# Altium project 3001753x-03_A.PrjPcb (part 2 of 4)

## Sheet 07 - Console, CAN, RS485, RTC.SchDoc: Console, CAN, RS485, RTC
size A3; PageSetup: Record=PageOptions¦CenterHorizontal=True¦CenterVertical=True¦PrintScale=0.70¦XCorrection=1.00¦YCorrection=1.00¦PrintKind=0¦BorderSize=5000000¦LeftOffset=0¦BottomOffset=0¦Orientation=2¦PaperLength=4200¦PaperWidth=2970¦Scale=100¦PaperSource=7¦PrintQuality=600¦MediaType=1¦DitherType=10¦PaperKind=A4¦PrintScaleMode=1; Author: Juan Anzola; SheetNumber: 7; SheetTotal: 20
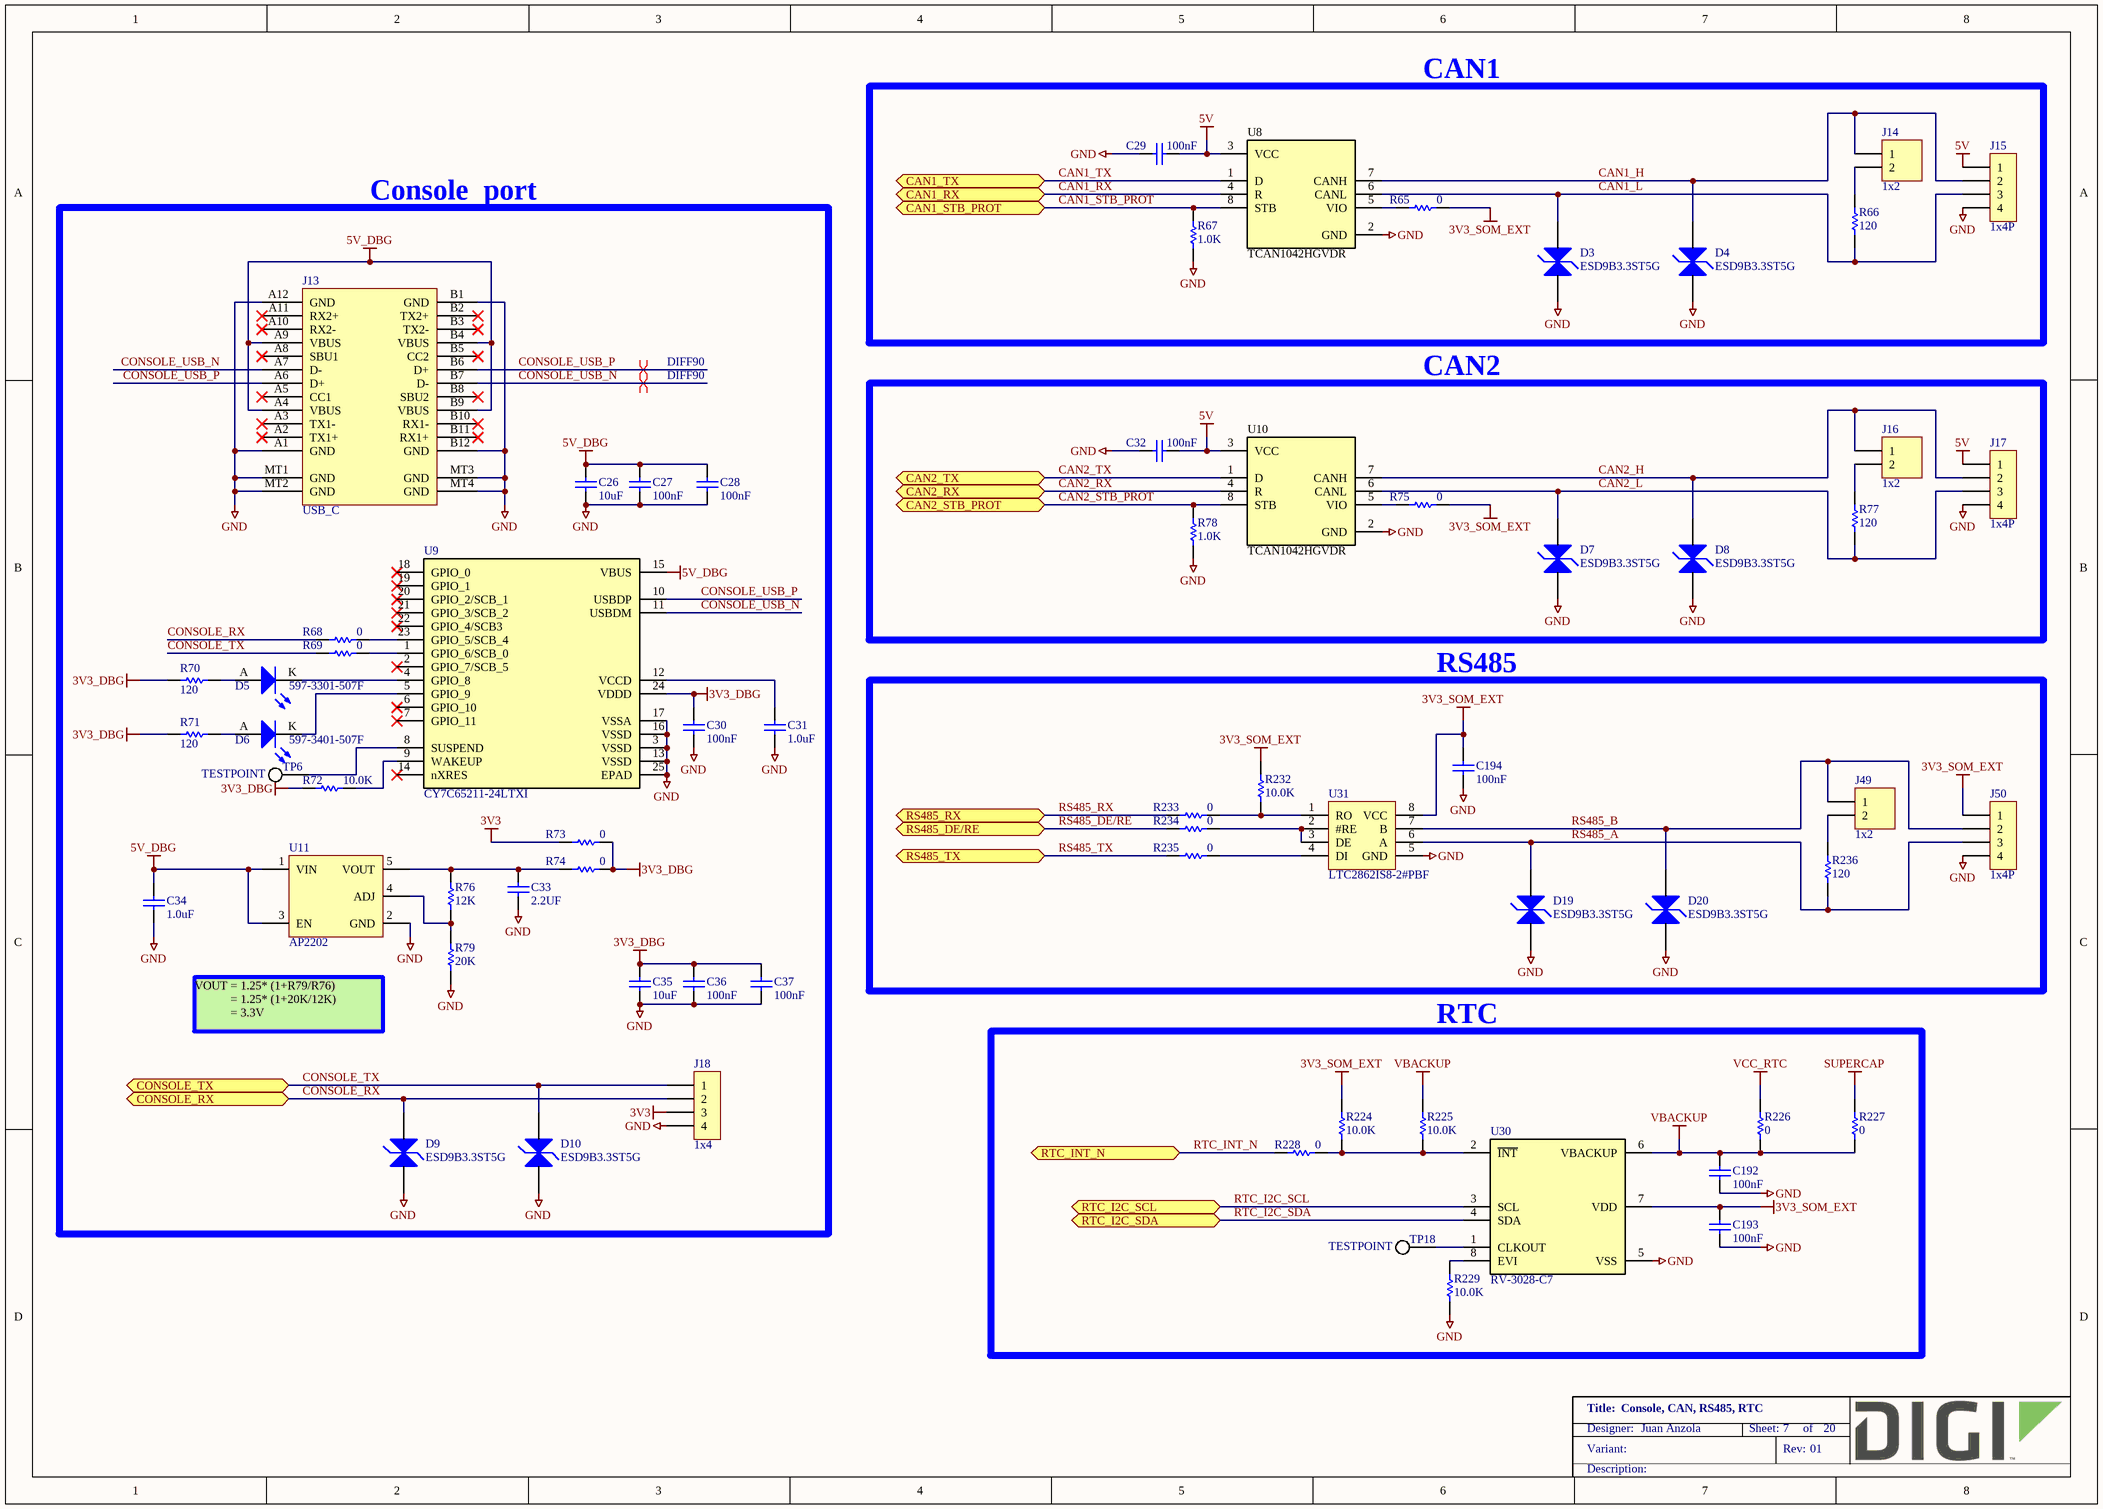
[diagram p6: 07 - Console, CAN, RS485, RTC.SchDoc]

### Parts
C26  10uF  [CAPC2013X135N]
C27  100nF  [CAPC1005X55N]
C28  100nF  [CAPC1005X55N]
C29  100nF  [CAPC1005X55N]
C30  100nF  [CAPC1005X55N]
C31  1.0uF  [CAPC1005X55N]
C32  100nF  [CAPC1005X55N]
C33  2.2UF  [CAPC1608X90N]
C34  1.0uF  [CAPC1005X55N]
C35  10uF  [CAPC2013X135N]
C36  100nF  [CAPC1005X55N]
C37  100nF  [CAPC1005X55N]
C192  100nF  [CAPC1005X55N]
C193  100nF  [CAPC1005X55N]
C194  100nF  [CAPC1005X55N]
D3  ESD9B3.3ST5G  [SODFL1006X43AN12]
D4  ESD9B3.3ST5G  [SODFL1006X43AN12]
D5  597-3301-507F  [LEDM3020X130N_GREEN]
D6  597-3401-507F  [LEDM3020X130N_YELLOW]
D7  ESD9B3.3ST5G  [SODFL1006X43AN12]
D8  ESD9B3.3ST5G  [SODFL1006X43AN12]
D9  ESD9B3.3ST5G  [SODFL1006X43AN12]
D10  ESD9B3.3ST5G  [SODFL1006X43AN12]
D19  ESD9B3.3ST5G  [SODFL1006X43AN12]
D20  ESD9B3.3ST5G  [SODFL1006X43AN12]
J13  USB_C  [MOLEX_201267-0005]
J14  1x2  [FCI_68002-102HLF]
J15  1x4P  [P4_STR_C2.54_H5.84]
J16  1x2  [FCI_68002-102HLF]
J17  1x4P  [P4_STR_C2.54_H5.84]
J18  1x4  [MOLEX_53047-0410]
J49  1x2  [FCI_68002-102HLF]
J50  1x4P  [P4_STR_C2.54_H5.84]
R65  0  [RESC1005X40N]
R66  120  [RESC1005X40N]
R67  1.0K  [RESC1005X40N]
R68  0  [RESC1005X40N]
R69  0  [RESC1005X40N]
R70  120  [RESC1005X40N]
R71  120  [RESC1005X40N]
R72  10.0K  [RESC1005X40N]
R73  0  [RESC1609X55N]
R74  0  [RESC1609X55N]
R75  0  [RESC1005X40N]
R76  12K  [RESC1609X55N]
R77  120  [RESC1005X40N]
R78  1.0K  [RESC1005X40N]
R79  20K  [RESC1609X55N]
R224  10.0K  [RESC1005X40N]
R225  10.0K  [RESC1005X40N]
R226  0  [RESC1005X40N]
R227  0  [RESC1005X40N]
R228  0  [RESC1005X40N]
R229  10.0K  [RESC1005X40N]
R232  10.0K  [RESC1005X40N]
R233  0  [RESC1005X40N]
R234  0  [RESC1005X40N]
R235  0  [RESC1005X40N]
R236  120  [RESC1005X40N]
TP6  TESTPOINT  [TP0762]  (no BOM)
TP18  TESTPOINT  [TP0762]  (no BOM)
U8  TCAN1042HGVDR  [SOIC127P600X175-8N]
U9  CY7C65211-24LTXI  [QFN50P400X400X100-25]
U10  TCAN1042HGVDR  [SOIC127P600X175-8N]
U11  AP2202  [SOT95P280X145-5N]
U30  RV-3028-C7  [DFN_8P_RV3028C7]
U31  LTC2862IS8-2#PBF  [SOIC127P600X175-8N]

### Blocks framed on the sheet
CAN1: C29 D3 D4 J14 J15 R65-R67 U8
Console  port: C26-C28 C30 C31 C33-C37 D5 D6 D9 D10 J13 J18 R68-R74 R76 R79 TP6 U9 U11
CAN2: C32 D7 D8 J16 J17 R75 R77 R78 U10
RS485: C194 D19 D20 J49 J50 R232-R236 U31
RTC: C192 C193 R224-R229 TP18 U30

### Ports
CAN1_RX (bidir), CAN1_STB_PROT (bidir), CAN1_TX (bidir), CAN2_RX (bidir), CAN2_STB_PROT (bidir), CAN2_TX (bidir), CONSOLE_RX (bidir), CONSOLE_TX (bidir), RS485_DE/RE (bidir), RS485_RX (bidir), RS485_TX (bidir), RTC_I2C_SCL (bidir), RTC_I2C_SDA (bidir), RTC_INT_N (bidir)

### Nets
3V3: J18.3 R73.1
3V3_DBG: C30.2 C35.2 C36.2 C37.2 R70.1 R71.1 R72.2 R73.2 R74.2 U9.24(VDDD)
3V3_SOM_EXT: C193.2 C194.2 J50.1 R65.2 R75.2 R224.2 R232.2 U30.7(VDD) U31.8(VCC)
5V: C29.1 C32.1 J15.1 J17.1 U8.3(VCC) U10.3(VCC)
5V_DBG: C26.2 C27.2 C28.2 C34.1 J13.A4(VBUS) J13.A9(VBUS) J13.B4(VBUS) J13.B9(VBUS) U9.15(VBUS) U11.1(VIN) U11.3(EN)
GND: C26.1 C27.1 C28.1 C29.2 C30.1 C31.2 C32.2 C33.1 C34.2 C35.1 C36.1 C37.1 C192.1 C193.1 C194.1 D3.1 D4.1 D7.1 D8.1 D9.1 D10.1 D19.1 D20.1 J13.A1(GND) J13.A12(GND) J13.B1(GND) J13.B12(GND) J13.MT1(GND) J13.MT2(GND) J13.MT3(GND) J13.MT4(GND) J15.4 J17.4 J18.4 J50.4 R67.1 R78.1 R79.1 R229.1 U8.2(GND) U9.3(VSSD) U9.13(VSSD) U9.16(VSSD) U9.17(VSSA) U9.25(EPAD) U10.2(GND) U11.2(GND) U30.5(VSS) U31.5(GND)
SUPERCAP: R227.2
VBACKUP: C192.2 R225.2 R226.1 R227.1 U30.6(VBACKUP)
VCC_RTC: R226.2
CAN1_H: D4.2 J14.1 J15.2 U8.7(CANH)
CAN1_L: D3.2 J15.3 R66.1 U8.6(CANL)
CAN1_RX: U8.4(R) ; port CAN1_RX
CAN1_STB_PROT: R67.2 U8.8(STB) ; port CAN1_STB_PROT
CAN1_TX: U8.1(D) ; port CAN1_TX
CAN2_H: D8.2 J16.1 J17.2 U10.7(CANH)
CAN2_L: D7.2 J17.3 R77.1 U10.6(CANL)
CAN2_RX: U10.4(R) ; port CAN2_RX
CAN2_STB_PROT: R78.2 U10.8(STB) ; port CAN2_STB_PROT
CAN2_TX: U10.1(D) ; port CAN2_TX
CONSOLE_RX: D9.2 J18.2 R68.1 ; port CONSOLE_RX
CONSOLE_TX: D10.2 J18.1 R69.1 ; port CONSOLE_TX
CONSOLE_USB_N: J13.A7(D-) J13.B7(D-) U9.11(USBDM)
CONSOLE_USB_P: J13.A6(D+) J13.B6(D+) U9.10(USBDP)
RS485_A: D19.2 J50.3 R236.1 U31.6(A)
RS485_B: D20.2 J49.1 J50.2 U31.7(B)
RS485_DE/RE: R234.1 ; port RS485_DE/RE
RS485_RX: R233.1 ; port RS485_RX
RS485_TX: R235.1 ; port RS485_TX
RTC_I2C_SCL: U30.3(SCL) ; port RTC_I2C_SCL
RTC_I2C_SDA: U30.4(SDA) ; port RTC_I2C_SDA
RTC_INT_N: R228.1 ; port RTC_INT_N
NetC31_1: C31.1 U9.12(VCCD)
NetC33_2: C33.2 R74.1 R76.2 U11.5(VOUT)
NetD5_A: D5.A R70.2
NetD5_K: D5.K U9.4(GPIO_8)
NetD6_A: D6.A R71.2
NetD6_K: D6.K U9.5(GPIO_9)
NetJ14_2: J14.2 R66.2
NetJ16_2: J16.2 R77.2
NetJ49_2: J49.2 R236.2
NetR65_1: R65.1 U8.5(VIO)
NetR68_2: R68.2 U9.23(GPIO_5/SCB_4)
NetR69_2: R69.2 U9.1(GPIO_6/SCB_0)
NetR72_1: R72.1 U9.9(WAKEUP)
NetR75_1: R75.1 U10.5(VIO)
NetR76_1: R76.1 R79.2 U11.4(ADJ)
NetR224_1: R224.1 R225.1 R228.2 U30.2(~{INT})
NetR229_2: R229.2 U30.8(EVI)
NetR232_1: R232.1 R233.2 U31.1(RO)
NetR234_2: R234.2 U31.2(#RE) U31.3(DE)
NetR235_2: R235.2 U31.4(DI)
NetTP6_1: TP6.1 U9.8(SUSPEND)
NetTP18_1: TP18.1 U30.1(CLKOUT)

Not connected (* = marked no-connect by the designer): J13 A2(TX1+)* A3(TX1-)* A5(CC1)* A8(SBU1)* A10(RX2-)* A11(RX2+)* B2(TX2+)* B3(TX2-)* B5(CC2)* B8(SBU2)* B10(RX1-)* B11(RX1+)*; U9 2(GPIO_7/SCB_5)* 6(GPIO_10)* 7(GPIO_11)* 14(nXRES)* 18(GPIO_0)* 19(GPIO_1)* 20(GPIO_2/SCB_1)* 21(GPIO_3/SCB_2)* 22(GPIO_4/SCB3)*

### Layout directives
differential pair; differential pair class DIFF90: CONSOLE_USB_N, CONSOLE_USB_P

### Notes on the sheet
- VOUT = 1.25* (1+R79/R76)
  = 1.25* (1+20K/12K)
  = 3.3V

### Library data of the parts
C26 C35 = 1000111: CAP CER 10UF 16V 10% X5R 0805; Part_Type: Capacitor; Manufacturer: Murata; Manufacturer_Part_Number: GRM21BR61C106KE15L; Digi_PN: 14050701; Component_Life_Cycle_State: Proven; Area: 3,99; Tolerance: 10
C27 C28 C192-C194 = 1000006: CAP 100nF 16V 10% X7R 0402; Part_Type: Capacitor; Manufacturer: Murata; Manufacturer_Part_Number: GRM155R71C104KA88D; Digi_PN: 14050552; Component_Life_Cycle_State: CAD Reviewed; Area: 0,95; Tolerance: 10
C29 C32 = 1000006: CAP 100nF 16V 10% X7R 0402; Part_Type: Capacitor; Manufacturer: Murata; Manufacturer_Part_Number: GRM155R71C104KA88D; Component_Life_Cycle_State: CAD Reviewed; Area: 0.95; Project: KITT; Tolerance: 10; Digi_PN: 14050552
C30 C36 C37 = 1000006: CAP 100nF 16V 10% X7R 0402; Part_Type: Capacitor; Manufacturer: Murata; Manufacturer_Part_Number: GRM155R71C104KA88D; Digi_PN: 14050552; Component_Life_Cycle_State: CAD Reviewed; Area: 0,95; Project: KITT; Tolerance: 10
C31 C34 = 1000073: CAP CER 1UF 6.3V 20% X5R 0402; Part_Type: Capacitor; Manufacturer: Murata; Manufacturer_Part_Number: GRM155R60J105ME19D; Digi_PN: 14050543; Component_Life_Cycle_State: Proven; Area: 0.95; Project: Adjustable Foundation
C33 = 1001303: CAP CER 2.2UF 16V 10% X5R 0603; Part_Type: Capacitor; Manufacturer: TDK Corporation; Manufacturer_Part_Number: C1608X5R1C225K080AB; Digi_PN: 14050730; Component_Life_Cycle_State: Reviewed; Area: 2,27
D3 D4 D7 D8 D19 D20 = 1001637: TVS DIODE 3.3VWM SOD923; Part_Type: Diodes; Manufacturer: On Semiconductor; Digi_PN: 17050883; Component_Life_Cycle_State: Reviewed; Area: 1,01
D5 = 1001189: LED GREEN 573NM 1208 SMD; Manufacturer: Dialight; Note: 17050846 = Digi PN for GE WDNU II; Digi_PN: 17050183; Component_Life_Cycle_State: Reviewed; Area: 6
D6 = 1001188: LED YELLOW 588NM 1208 SMD; Manufacturer: Dialight; Note: 17050842 = Digi No. for GE WDNU; Digi_PN: 17050387; Component_Life_Cycle_State: Reviewed; Area: 6
D9 D10 = 1001637: TVS DIODE 3.3VWM SOD923; Part_Type: Diodes; Manufacturer: On Semiconductor; Digi_PN: 17050883; Component_Life_Cycle_State: Reviewed; Area: 1,01; Project: CareTaker IV
J13 = 1002675: USB 3.1 SHIELDED I/O RECP TYPE C GEN2; Part_Type: Connector; Manufacturer: Molex; Manufacturer_Part_Number: 201267-0005; Digi_PN: 18000775; Component_Life_Cycle_State: Reviewed; Area: 91,35
J14 J16 J49 = 1001128: CONN HEADER 2POS .100" SGL GOLD; Part_Type: Connector; Manufacturer: Samtec; Manufacturer_Part_Number: TSW-102-07-G-S; Digi_PN: 00120002; Component_Life_Cycle_State: Reviewed; Area: 12,9032
J15 J17 J50 = 1002860: CONN HEADER VERT 4POS 2.54MM; Part_Type: Connector; Manufacturer: Samtec; Manufacturer_Part_Number: TSW-104-07-G-S; Digi_PN: 00120004; Component_Life_Cycle_State: Pending
J18 = 1001137: CONN HEADER 4POS 1.25MM VERT TIN; Part_Type: Connector; Manufacturer: Molex; Manufacturer_Part_Number: 53047-0410; Digi_PN: 18050344; Component_Life_Cycle_State: Reviewed; Area: 21,6
R65 R69 R75 = 1000076: RES 0.0 OHM 1/10W 0402 SMD; Part_Type: Resistor; Manufacturer: Panasonic - ECG; Manufacturer_Part_Number: ERJ-2GE0R00X; Component_Life_Cycle_State: Proven; Area: 0.95; Project: Adjustable Foundation; Power_WV_SRF: 10; Digi_PN: 13050387
R66 R70 R71 R77 = 1001158: RES 120 OHM 1/16W 1% 0402 SMD; Part_Type: Resistor; Manufacturer: Yageo; Manufacturer_Part_Number: RC0402FR-07120RL; Digi_PN: 13050832; Component_Life_Cycle_State: Reviewed; Area: 0.95; Project: CCWMX6_SBC board; Note: 13051102 = Digi No. for GE WDNU
R67 R78 = 1000079: RES 1.00K OHM 1/10W 1% 0402 SMD; Part_Type: Resistor; Manufacturer: Panasonic - ECG; Manufacturer_Part_Number: ERJ-2RKF1001X; Digi_PN: 13051085; Component_Life_Cycle_State: Proven; Area: 0,95; Project: Adjustable Foundation; Power_WV_SRF: 10
R68 R226-R228 R233-R235 = 1000076: RES 0.0 OHM 1/10W 0402 SMD; Part_Type: Resistor; Manufacturer: Panasonic - ECG; Manufacturer_Part_Number: ERJ-2GE0R00X; Digi_PN: 13050387; Component_Life_Cycle_State: Proven; Area: 0,95; Power_WV_SRF: 10
R72 = 1000537: RES 10.0K OHM 1/10W 1% 0402 SMD; Part_Type: Resistor; Manufacturer: Panasonic - ECG; Manufacturer_Part_Number: ERJ-2RKF1002X; Component_Life_Cycle_State: CAD Reviewed; Area: 0.95; Project: KITT; Power_WV_SRF: 100; Digi_PN: 13051084
R73 R74 = 1000208: RES 0.0 OHM 1/10W 0603; Part_Type: Resistor; Manufacturer: Panasonic - ECG; Manufacturer_Part_Number: ERJ-3GEY0R00V; Note: 13051103 = Digi No. for GE WDNU; Digi_PN: 13050568; Component_Life_Cycle_State: Reviewed; Area: 2,5; Voltage: 75V
R76 = 1001200: RES 12.0K OHM 1/10W 1% 0603 SMD; Part_Type: Resistor; Manufacturer: Yageo; Manufacturer_Part_Number: RC0603FR-0712KL; Digi_PN: 13050531; Component_Life_Cycle_State: Reviewed; Area: 2,5; Power_WV_SRF: 100; Tolerance: 1
R79 = 1000142: RES 20K OHM 1/10W 5% 0603 SMD; Part_Type: Resistor; Manufacturer: Panasonic - ECG; Manufacturer_Part_Number: ERJ-3GEYJ203V; Digi_PN: 13050013; Component_Life_Cycle_State: Reviewed; Area: 2,5; Power_WV_SRF: 100; Tolerance: 5
R224 R225 R229 R232 = 1000537: RES 10.0K OHM 1/10W 1% 0402 SMD; Part_Type: Resistor; Manufacturer: Panasonic - ECG; Manufacturer_Part_Number: ERJ-2RKF1002X; Digi_PN: 13051084; Component_Life_Cycle_State: CAD Reviewed; Area: 0,95; Power_WV_SRF: 100
R236 = 1001158: RES 120 OHM 1/16W 1% 0402 SMD; Part_Type: Resistor; Manufacturer: Yageo; Manufacturer_Part_Number: RC0402FR-07120RL; Note: 13051102 = Digi No. for GE WDNU; Digi_PN: 13050832; Component_Life_Cycle_State: Reviewed; Area: 0,95
TP6 = CAD0011: TEST POINT 30mil PAD SMT; Component_Life_Cycle_State: Reviewed; Area: 0.58; Project: CLC
TP18 = CAD0011: TEST POINT 30MIL PAD SMT; Component_Life_Cycle_State: Reviewed; Area: 0,58
U8 U10 = 1002681: IC CAN TRANSEIVER HS 8SOIC; Manufacturer: Texas Instruments; Digi_PN: 16000166; Component_Life_Cycle_State: Pending; Area: 20; Project: DIGI CC8X SOM
U9 = 1002827: IC USB TO SERIAL BRIDGE 24QFN; Manufacturer: Cypress Semiconductor; Digi_PN: 16000439; Component_Life_Cycle_State: Pending
U11 = 1001979: IC REG LDO ADJ 0.15A SOT25; Part_Type: Regulator; Manufacturer: Diodes, Inc.; Manufacturer_Part_Number: AP2202K-ADJTRG1; Digi_PN: 17050874; Component_Life_Cycle_State: Reviewed; Area: 14,92
U30 = 1002829: SMIC, RTC, I2C, RV-3028-C7, 45n@3V, DFN-8, -40/+85°C; Manufacturer_Name: Micro Crystal AG; Manufacturer_Part_Number: RV-3028-C7 32.768kHz 1ppm TA QC; Part_Type: IC; Manufacturer: Micro Commercial Co; Digi_PN: 16000441; Component_Life_Cycle_State: Created; Area: 4,8
U31 = 1001420: IC TRANSCEIVER RS485 8-SOIC; Manufacturer: Linear Technology; Digi_PN: 16052092; Component_Life_Cycle_State: Reviewed; Area: 34,75

## Sheet 08 - JTAG, SWD, uSD, Mini PCIe, uSIM.SchDoc: JTAG, SWD, uSD, Mini PCIe, uSIM
size A3; PageSetup: Record=PageOptions¦CenterHorizontal=True¦CenterVertical=True¦PrintScale=0.70¦XCorrection=1.00¦YCorrection=1.00¦PrintKind=0¦BorderSize=5000000¦LeftOffset=0¦BottomOffset=0¦Orientation=2¦PaperLength=4200¦PaperWidth=2970¦Scale=100¦PaperSource=7¦PrintQuality=600¦MediaType=1¦DitherType=10¦PaperKind=A4¦PrintScaleMode=1; Author: Juan Anzola; SheetNumber: 8; SheetTotal: 20
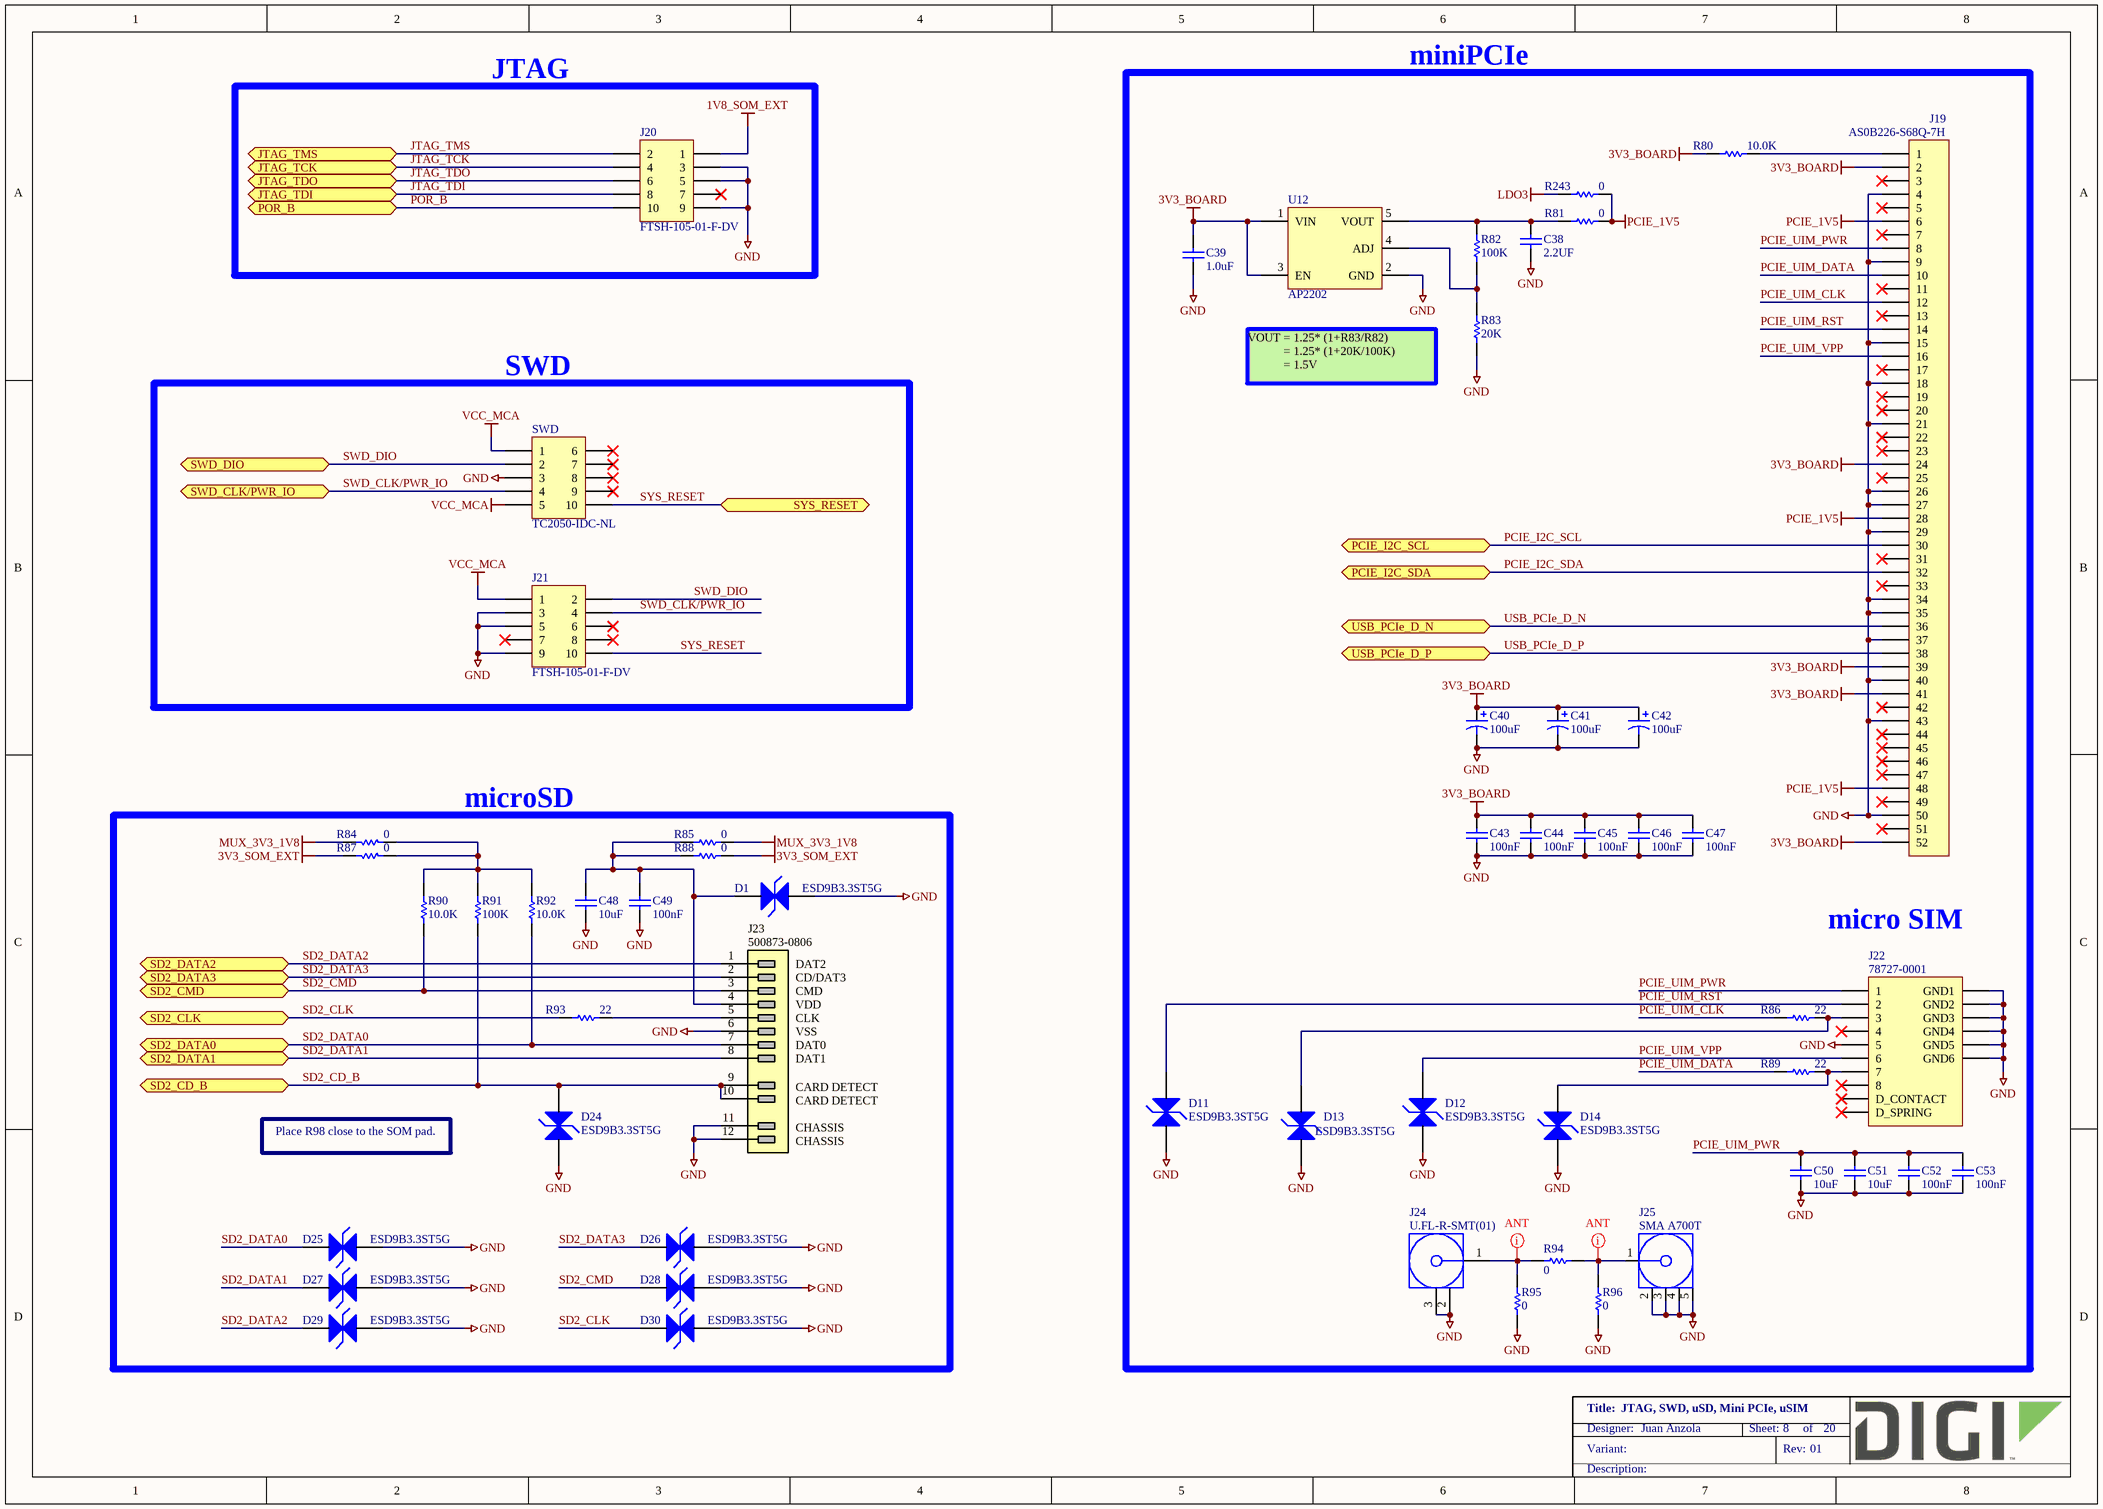
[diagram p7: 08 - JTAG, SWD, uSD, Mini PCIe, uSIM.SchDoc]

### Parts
C38  2.2UF  [CAPC1608X90N]
C39  1.0uF  [CAPC1005X55N]
C40  100uF  [CAPMP3216X120N]
C41  100uF  [CAPMP3216X120N]
C42  100uF  [CAPMP3216X120N]
C43  100nF  [CAPC1005X55N]
C44  100nF  [CAPC1005X55N]
C45  100nF  [CAPC1005X55N]
C46  100nF  [CAPC1005X55N]
C47  100nF  [CAPC1005X55N]
C48  10uF  [CAPC1005X55N]
C49  100nF  [CAPC1005X55N]
C50  10uF  [CAPC2013X135N]
C51  10uF  [CAPC2013X135N]
C52  100nF  [CAPC1005X55N]
C53  100nF  [CAPC1005X55N]
D1  ESD9B3.3ST5G  [SODFL1006X43AN12]
D11  ESD9B3.3ST5G  [SODFL1006X43AN12]
D12  ESD9B3.3ST5G  [SODFL1006X43AN12]
D13  ESD9B3.3ST5G  [SODFL1006X43AN12]
D14  ESD9B3.3ST5G  [SODFL1006X43AN12]
D24  ESD9B3.3ST5G  [SODFL1006X43AN12]
D25  ESD9B3.3ST5G  [SODFL1006X43AN12]
D26  ESD9B3.3ST5G  [SODFL1006X43AN12]
D27  ESD9B3.3ST5G  [SODFL1006X43AN12]
D28  ESD9B3.3ST5G  [SODFL1006X43AN12]
D29  ESD9B3.3ST5G  [SODFL1006X43AN12]
D30  ESD9B3.3ST5G  [SODFL1006X43AN12]
J19  Manufacturer_Part_Number: AS0B226-S68Q-7H  [FOXCONN_AS0B221-S68Q-7H]  (hidden comment: PCIe Minicard)
J20  FTSH-105-01-F-DV  [SAMTEC_FTSH-105-01-F-DV]
J21  FTSH-105-01-F-DV  [SAMTEC_FTSH-105-01-F-DV]
J22  78727-0001  [MOLEX_78727-0001]
J23  500873-0806  [MOLEX_500873-0806]
J24  U.FL-R-SMT(01)  [HIROSE_U.FL-R-SMT(01)]
J25  SMA A700T  [BOBBINTRON_SMA A700T]
R80  10.0K  [RESC1005X40N]
R81  0  [RESC1005X40N]
R82  100K  [RESC1005X40N]
R83  20K  [RESC1609X55N]
R84  0  [RESC1005X40N]
R85  0  [RESC1005X40N]
R86  22  [RESC1005X40N]
R87  0  [RESC1005X40N]
R88  0  [RESC1005X40N]
R89  22  [RESC1005X40N]
R90  10.0K  [RESC1005X40N]
R91  100K  [RESC1005X40N]
R92  10.0K  [RESC1005X40N]
R93  22  [RESC1005X40N]
R94  0  [RESC1005X40N]
R95  0  [RESC1005X40N]
R96  0  [RESC1005X40N]
R243  0  [RESC1005X40N]
SWD  TC2050-IDC-NL  [TC_TC2050-IDC-NL]  (no BOM)
U12  AP2202  [SOT95P280X145-5N]

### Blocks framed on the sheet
JTAG: J20
SWD: J21 SWD
microSD: C48 C49 D1 D24-D30 J23 R84 R85 R87 R88 R90-R93

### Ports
JTAG_TCK (bidir), JTAG_TDI (bidir), JTAG_TDO (bidir), JTAG_TMS (bidir), PCIE_I2C_SCL (bidir), PCIE_I2C_SDA (bidir), POR_B (bidir), SD2_CD_B (bidir), SD2_CLK (bidir), SD2_CMD (bidir), SD2_DATA0 (bidir), SD2_DATA1 (bidir), SD2_DATA2 (bidir), SD2_DATA3 (bidir), SWD_CLK/PWR_IO (bidir), SWD_DIO (bidir), SYS_RESET (bidir), USB_PCIe_D_N (bidir), USB_PCIe_D_P (bidir)

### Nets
1V8_SOM_EXT: J20.1
3V3_BOARD: C39.1 C40.1 C41.1 C42.1 C43.2 C44.2 C45.2 C46.2 C47.2 J19.2 J19.24 J19.39 J19.41 J19.52 R80.2 U12.1(VIN) U12.3(EN)
3V3_SOM_EXT: R87.2 R88.2
GND: C38.1 C39.2 C40.2 C41.2 C42.2 C43.1 C44.1 C45.1 C46.1 C47.1 C48.1 C49.1 C50.1 C51.1 C52.1 C53.1 D1.2 D11.1 D12.1 D13.1 D14.1 D24.2 D25.2 D26.2 D27.2 D28.2 D29.2 D30.2 J19.4 J19.9 J19.15 J19.18 J19.21 J19.26 J19.27 J19.29 J19.34 J19.35 J19.37 J19.40 J19.43 J19.50 J20.3 J20.5 J20.9 J21.3 J21.5 J21.9 J22.5 J22.11(GND1) J22.12(GND2) J22.13(GND3) J22.14(GND4) J22.15(GND5) J22.16(GND6) J23.6 J23.11 J23.12 J24.2(GND) J24.3(GND) J25.2(GND) J25.3(GND) J25.4(GND) J25.5(GND) R83.1 R95.1 R96.1 SWD.3 U12.2(GND)
LDO3: R243.1
MUX_3V3_1V8: R84.2 R85.2
PCIE_1V5: J19.6 J19.28 J19.48 R81.2 R243.2
VCC_MCA: J21.1 SWD.1 SWD.5
JTAG_TCK: J20.4 ; port JTAG_TCK
JTAG_TDI: J20.8 ; port JTAG_TDI
JTAG_TDO: J20.6 ; port JTAG_TDO
JTAG_TMS: J20.2 ; port JTAG_TMS
PCIE_I2C_SCL: J19.30 ; port PCIE_I2C_SCL
PCIE_I2C_SDA: J19.32 ; port PCIE_I2C_SDA
PCIE_UIM_CLK: J19.12 R86.1
PCIE_UIM_DATA: J19.10 R89.1
PCIE_UIM_PWR: C50.2 C51.2 C52.2 C53.2 J19.8 J22.1
PCIE_UIM_RST: D11.2 J19.14 J22.2
PCIE_UIM_VPP: D12.2 J19.16 J22.6
POR_B: J20.10 ; port POR_B
SD2_CD_B: D24.1 J23.9 J23.10 R91.2 ; port SD2_CD_B
SD2_CLK: D30.1 R93.1 ; port SD2_CLK
SD2_CMD: D28.1 J23.3 R90.1 ; port SD2_CMD
SD2_DATA0: D25.1 J23.7 R92.1 ; port SD2_DATA0
SD2_DATA1: D27.1 J23.8 ; port SD2_DATA1
SD2_DATA2: D29.1 J23.1 ; port SD2_DATA2
SD2_DATA3: D26.1 J23.2 ; port SD2_DATA3
SWD_CLK/PWR_IO: J21.4 SWD.4 ; port SWD_CLK/PWR_IO
SWD_DIO: J21.2 SWD.2 ; port SWD_DIO
SYS_RESET: J21.10 SWD.10 ; port SYS_RESET
USB_PCIe_D_N: J19.36 ; port USB_PCIe_D_N
USB_PCIe_D_P: J19.38 ; port USB_PCIe_D_P
NetC38_2: C38.2 R81.1 R82.2 U12.5(VOUT)
NetC48_2: C48.2 C49.2 D1.1 J23.4 R85.1 R88.1
NetD13_2: D13.2 J22.3 R86.2
NetD14_2: D14.2 J22.7 R89.2
NetJ19_1: J19.1 R80.1
NetJ23_5: J23.5 R93.2
NetJ24_1: J24.1(Signal) R94.1 R95.2
NetJ25_1: J25.1(Signal) R94.2 R96.2
NetR82_1: R82.1 R83.2 U12.4(ADJ)
NetR84_1: R84.1 R87.1 R90.2 R91.1 R92.2

Not connected (* = marked no-connect by the designer): J19 3* 5* 7* 11* 13* 17* 19* 20* 22* 23* 25* 31* 33* 42* 44* 45* 46* 47* 49* 51*; J20 7*; J21 6* 7* 8*; J22 4* 8* 9(D_CONTACT)* 10(D_SPRING)*; SWD 6* 7* 8* 9*

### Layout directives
net class ANT: NetJ24_1, NetJ25_1

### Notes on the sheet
- miniPCIe
- VOUT = 1.25* (1+R83/R82)
  = 1.25* (1+20K/100K)
  = 1.5V
- micro SIM
- Place R98 close to the SOM pad.

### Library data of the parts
C38 = 1001303: as C33 on sheet 07 - Console, CAN, RS485, RTC
C39 = 1001167: CAP CER 1UF 10V 10% X5R 0402; Part_Type: Capacitor; Manufacturer: Murata; Manufacturer_Part_Number: GRM155R61A105KE15D; Digi_PN: 14050399; Component_Life_Cycle_State: Reviewed; Area: 0,95
C40-C42 = 1001196: CAP TANT 100UF 6.3V 20% 1206; Part_Type: Capacitor; Manufacturer: Rohm; Manufacturer_Part_Number: TCTAL0J107M8R; Digi_PN: 14050490; Component_Life_Cycle_State: Reviewed; Area: 8.01; Project: CCWMX6_SBC board
C43-C47 C49 C52 C53 = 1000006: as C29 on sheet 07 - Console, CAN, RS485, RTC
C48 = 1001168: CAP CER 10UF 10V 20% X5R 0402; Part_Type: Capacitor; Manufacturer: Samsung; Manufacturer_Part_Number: CL05A106MP5NUNC; Digi_PN: 14050689; Component_Life_Cycle_State: Reviewed; Area: 0.95; Project: CCWMX6_SBC board
C50 C51 = 1000111: CAP CER 10UF 16V 10% X5R 0805; Part_Type: Capacitor; Manufacturer: Murata; Manufacturer_Part_Number: GRM21BR61C106KE15L; Digi_PN: 14050701; Component_Life_Cycle_State: Proven; Area: 3.99; Project: Adjustable Foundation; Tolerance: 10
D1 D11-D14 D24-D30 = 1001637: as D3 on sheet 07 - Console, CAN, RS485, RTC
J19 = 1001130: SMCONN,MINI PCI EXP, 6.8MM HT; Part_Type: Connector; Manufacturer: Foxconn; Digi_PN: 18000349; Component_Life_Cycle_State: Reviewed; Area: 150; Project: CCWMX6_SBC board
J20 = 1000034: CONN HEADER 10POS DUAL .05" SMD; Part_Type: Connector; Manufacturer: Samtec; Note: 18000715 = Digi No. for GE WDNU; Digi_PN: 18000539; Component_Life_Cycle_State: Proven; Area: 43.55; Project: Adjustable Foundation
J21 = 1000034: CONN HEADER 10POS DUAL .05" SMD; Part_Type: Connector; Manufacturer: Samtec; Note: 18000715 = Digi No. for GE WDNU; Digi_PN: 18000539; Component_Life_Cycle_State: Proven; Area: 43,55; Project: Adjustable Foundation
J22 = 1001120: MEMORY CARD 6POS PUSH/PULL SMD; Part_Type: Connector; Manufacturer: Molex; Digi_PN: 18000638; Component_Life_Cycle_State: Reviewed; Area: 217; Project: CCWMX6_SBC board
J23 = 1001118: CONN TRANSFLSH R/A PUSH-PUSH SMD; Part_Type: Connector; Manufacturer: Molex; Digi_PN: MB03015; Component_Life_Cycle_State: Reviewed; Area: 213; Project: CCWMX6_SBC board
J24 = 1000027: RF Connectors U.FL RECEPTACLE SMT GLD M CONTACT; Manufacturer: Hirose; Digi_PN: 18000684; Component_Life_Cycle_State: Proven; Area: 14,4
J25 = 1002720: CONN SMA JACK R/A 50 OHM L15.1MM PCB TH; Part_Type: Connector; Manufacturer: Bobbintron Electrical Corp; Digi_PN: MA02979; Component_Life_Cycle_State: Reviewed; Area: 121,68
R80 R90 R92 = 1000537: as R72 on sheet 07 - Console, CAN, RS485, RTC
R81 R94-R96 R243 = 1000076: as R68 on sheet 07 - Console, CAN, RS485, RTC
R82 = 1000480: RES 100K OHM 1/10W 1% 0402 SMD; Part_Type: Resistor; Manufacturer: Panasonic - ECG; Manufacturer_Part_Number: ERJ-2RKF1003X; Digi_PN: 13051063; Component_Life_Cycle_State: CAD Reviewed; Area: 0,95; Power_WV_SRF: 100
R83 = 1000142: as R79 on sheet 07 - Console, CAN, RS485, RTC
R84 R85 R87 R88 = 1000076: as R65 on sheet 07 - Console, CAN, RS485, RTC
R86 R89 R93 = 1000601: RES 22.0 OHM 1/10W 1% 0402 SMD; Part_Type: Resistor; Manufacturer: Panasonic - ECG; Manufacturer_Part_Number: ERJ-2RKF22R0X; Digi_PN: 13051089; Component_Life_Cycle_State: CAD Reviewed; Area: 0,95; Power_WV_SRF: 100
R91 = 1000480: RES 100K OHM 1/10W 1% 0402 SMD; Part_Type: Resistor; Manufacturer: Panasonic - ECG; Manufacturer_Part_Number: ERJ-2RKF1003X; Digi_PN: 13051063; Component_Life_Cycle_State: CAD Reviewed; Area: 0.95; Project: KITT; Power_WV_SRF: 100
SWD = CAD0066: CBL PLUG-OF-NAILS 10-PIN; Part_Type: Test Point; Component_Life_Cycle_State: Created; Area: 8; Project: CCWMX6_SBC board
U12 = 1001979: as U11 on sheet 07 - Console, CAN, RS485, RTC

## Sheet 09 - Gigabit Ethernet 1.SchDoc: Gigabit Ethernet 1
size A3; PageSetup: Record=PageOptions¦CenterHorizontal=True¦CenterVertical=True¦PrintScale=0.70¦XCorrection=1.00¦YCorrection=1.00¦PrintKind=0¦BorderSize=5000000¦LeftOffset=0¦BottomOffset=0¦Orientation=2¦PaperLength=4200¦PaperWidth=2970¦Scale=100¦PaperSource=7¦PrintQuality=600¦MediaType=1¦DitherType=10¦PaperKind=A4¦PrintScaleMode=1; Author: Juan Anzola; SheetNumber: 9; SheetTotal: 20
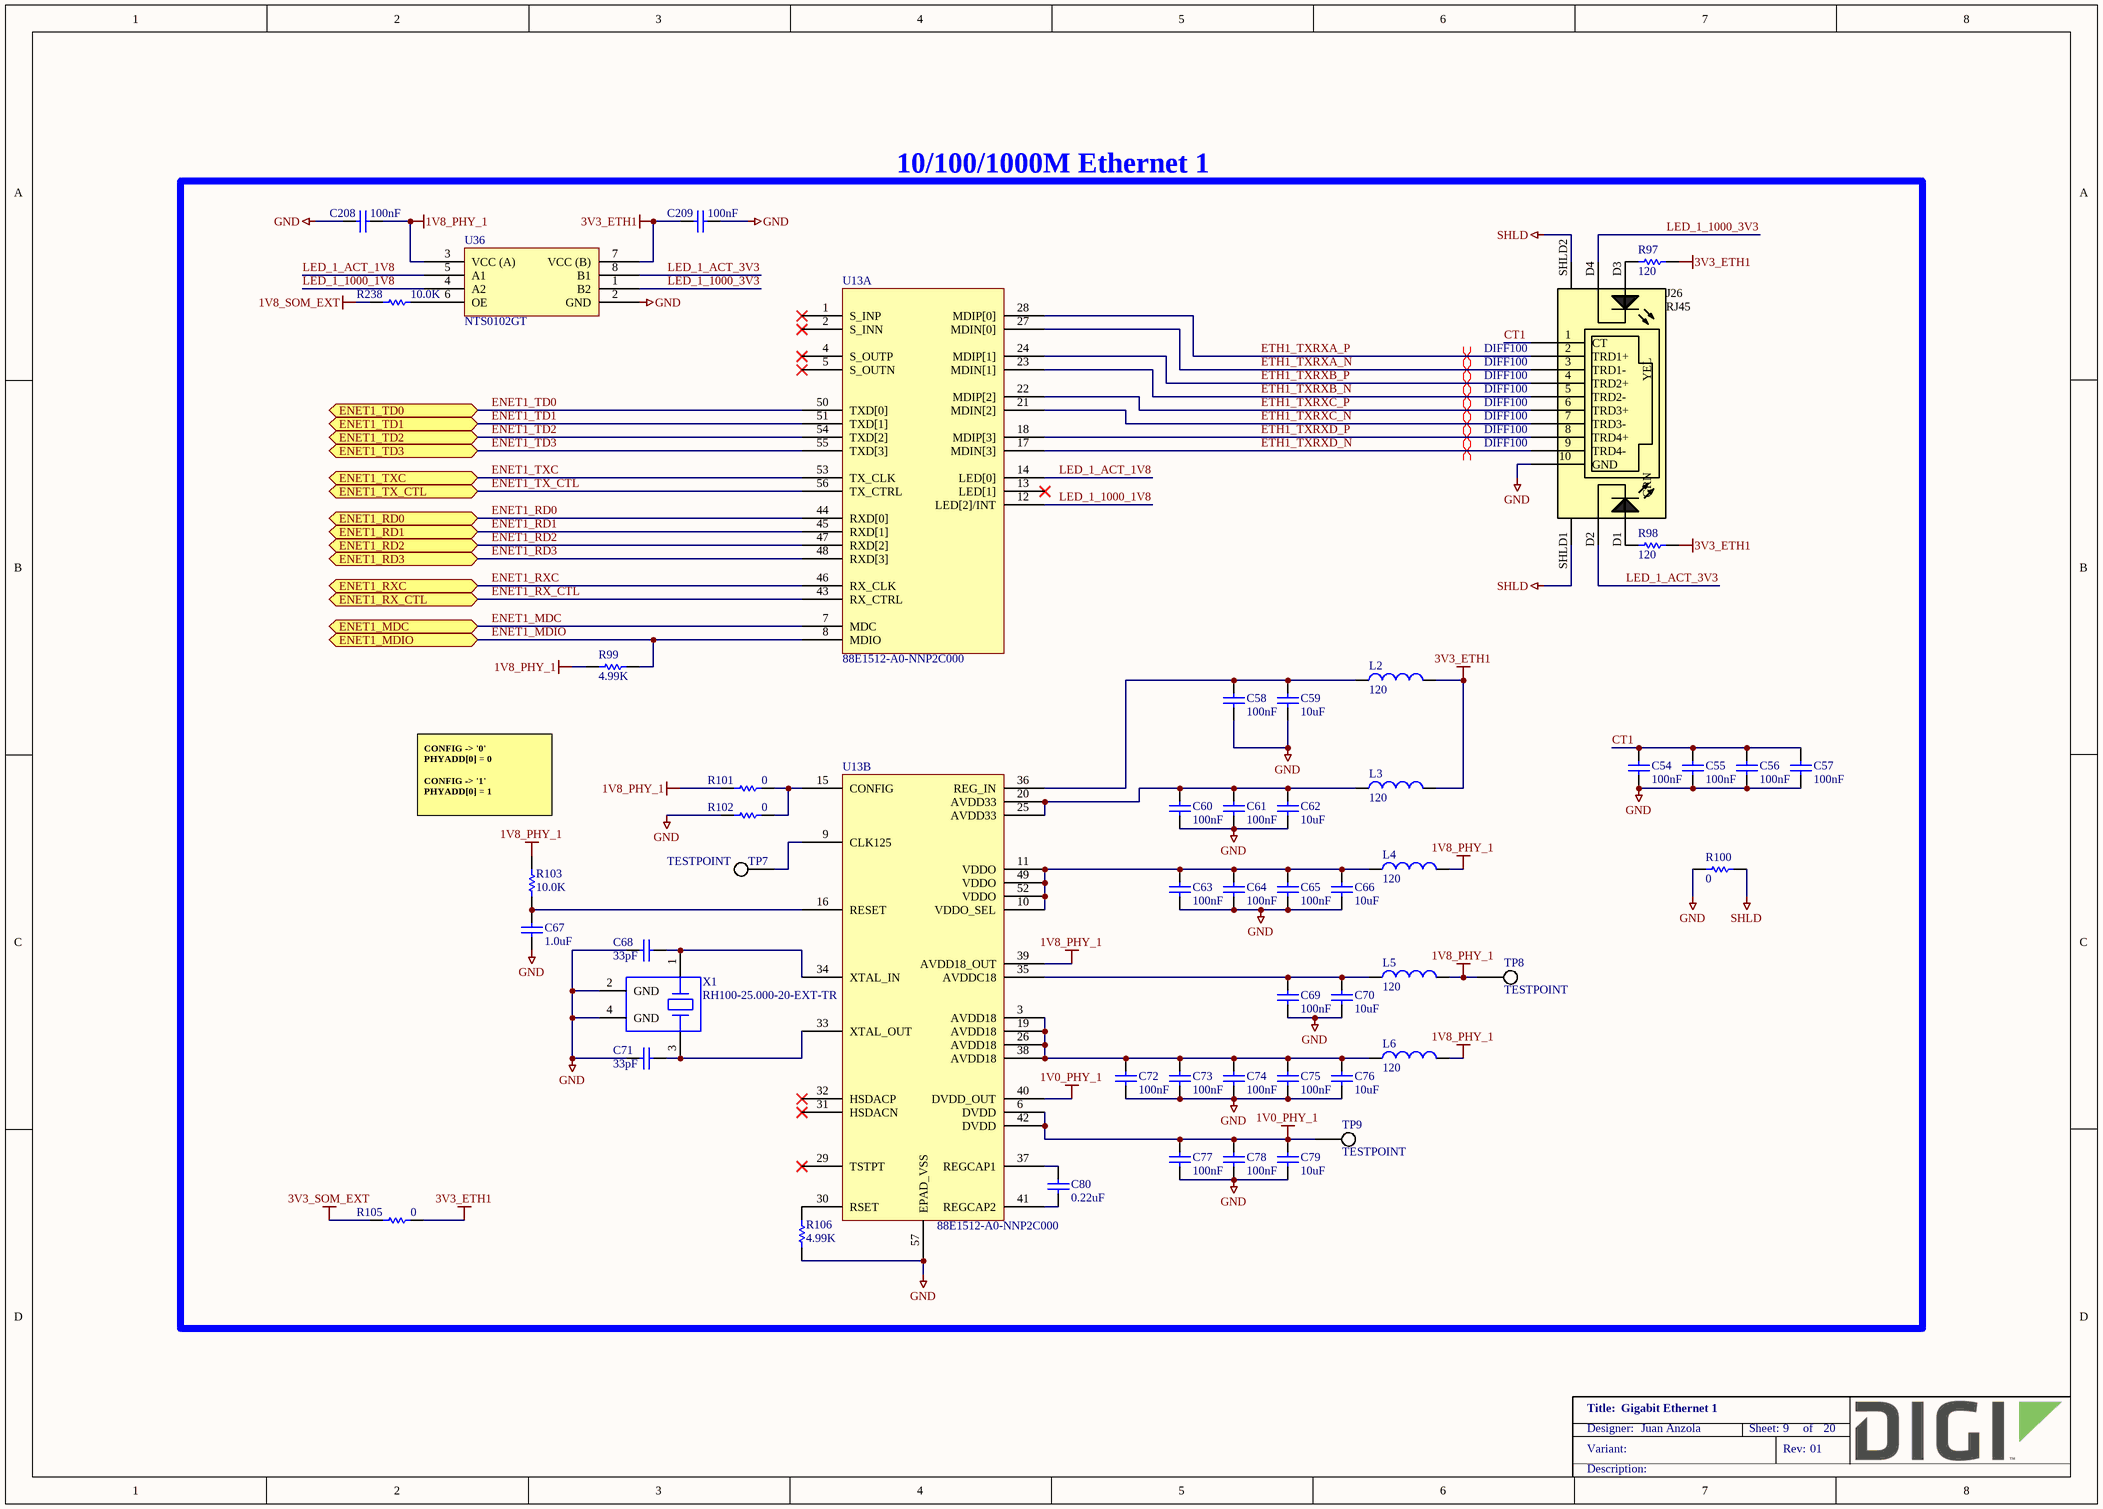
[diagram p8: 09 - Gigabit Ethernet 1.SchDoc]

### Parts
C54  100nF  [CAPC1005X55N]
C55  100nF  [CAPC1005X55N]
C56  100nF  [CAPC1005X55N]
C57  100nF  [CAPC1005X55N]
C58  100nF  [CAPC1005X55N]
C59  10uF  [CAPC2013X135N]
C60  100nF  [CAPC1005X55N]
C61  100nF  [CAPC1005X55N]
C62  10uF  [CAPC2013X135N]
C63  100nF  [CAPC1005X55N]
C64  100nF  [CAPC1005X55N]
C65  100nF  [CAPC1005X55N]
C66  10uF  [CAPC2013X135N]
C67  1.0uF  [CAPC1005X55N]
C68  33pF  [CAPC1005X55N]
C69  100nF  [CAPC1005X55N]
C70  10uF  [CAPC2013X135N]
C71  33pF  [CAPC1005X55N]
C72  100nF  [CAPC1005X55N]
C73  100nF  [CAPC1005X55N]
C74  100nF  [CAPC1005X55N]
C75  100nF  [CAPC1005X55N]
C76  10uF  [CAPC2013X135N]
C77  100nF  [CAPC1005X55N]
C78  100nF  [CAPC1005X55N]
C79  10uF  [CAPC2013X135N]
C80  0.22uF  [CAPC1005X55N]
C208  100nF  [CAPC1005X55N]
C209  100nF  [CAPC1005X55N]
J26  RJ45  [XMULTIPLE_XMG-J1B211]
L2  120  [INDC1005X60N]
L3  120  [INDC1005X60N]
L4  120  [INDC1005X60N]
L5  120  [INDC1005X60N]
L6  120  [INDC1005X60N]
R97  120  [RESC1005X40N]
R98  120  [RESC1005X40N]
R99  4.99K  [RESC1005X40N]
R100  0  [RESC3225X60N]
R101  0  [RESC1609X55N]
R102  0  [RESC1609X55N]
R103  10.0K  [RESC1005X40N]
R105  0  [RESC1609X55N]
R106  4.99K  [RESC1005X40N]
R238  10.0K  [RESC1005X40N]
TP7  TESTPOINT  [TP0762]  (no BOM)
TP8  TESTPOINT  [TP0762]  (no BOM)
TP9  TESTPOINT  [TP0762]  (no BOM)
U13  88E1512-A0-NNP2C000  [QFN56P8mmx8mm-4.50mmPAD]  (parts A,B of 2)
U36  NTS0102GT  [PSON50P195X100X50-8N]
X1  RH100-25.000-20-EXT-TR  [OSC210P320X250X90-4N]

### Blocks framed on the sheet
10/100/1000M Ethernet 1: C54-C80 C208 C209 J26 L2-L6 R97-R103 R105 R106 R238 TP7-TP9 U13 U36 X1

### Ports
ENET1_MDC (bidir), ENET1_MDIO (bidir), ENET1_RD0 (bidir), ENET1_RD1 (bidir), ENET1_RD2 (bidir), ENET1_RD3 (bidir), ENET1_RX_CTL (bidir), ENET1_RXC (bidir), ENET1_TD0 (bidir), ENET1_TD1 (bidir), ENET1_TD2 (bidir), ENET1_TD3 (bidir), ENET1_TX_CTL (bidir), ENET1_TXC (bidir)

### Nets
1V0_PHY_1: C77.2 C78.2 C79.2 TP9.1 U13.6(DVDD) U13.40(DVDD_OUT) U13.42(DVDD)
1V8_PHY_1: C208.2 L4.2 L5.2 L6.2 R99.1 R101.1 R103.2 TP8.1 U13.39(AVDD18_OUT) U36.3(VCC_(A))
1V8_SOM_EXT: R238.1
3V3_ETH1: C209.1 L2.2 L3.2 R97.1 R98.1 R105.2 U36.7(VCC_(B))
3V3_SOM_EXT: R105.1
GND: C54.1 C55.1 C56.1 C57.1 C58.1 C59.1 C60.1 C61.1 C62.1 C63.1 C64.1 C65.1 C66.1 C67.2 C68.1 C69.1 C70.1 C71.1 C72.1 C73.1 C74.1 C75.1 C76.1 C77.1 C78.1 C79.1 C208.1 C209.2 J26.10(GND) R100.1 R102.1 R106.1 U13.57(EPAD_VSS) U36.2(GND) X1.2(GND) X1.4(GND)
SHLD: J26.SHLD1(SHLD) J26.SHLD2(SHLD) R100.2
CT1: C54.2 C55.2 C56.2 C57.2 J26.1(CT)
ENET1_MDC: U13.7(MDC) ; port ENET1_MDC
ENET1_MDIO: R99.2 U13.8(MDIO) ; port ENET1_MDIO
ENET1_RD0: U13.44(RXD[0]) ; port ENET1_RD0
ENET1_RD1: U13.45(RXD[1]) ; port ENET1_RD1
ENET1_RD2: U13.47(RXD[2]) ; port ENET1_RD2
ENET1_RD3: U13.48(RXD[3]) ; port ENET1_RD3
ENET1_RX_CTL: U13.43(RX_CTRL) ; port ENET1_RX_CTL
ENET1_RXC: U13.46(RX_CLK) ; port ENET1_RXC
ENET1_TD0: U13.50(TXD[0]) ; port ENET1_TD0
ENET1_TD1: U13.51(TXD[1]) ; port ENET1_TD1
ENET1_TD2: U13.54(TXD[2]) ; port ENET1_TD2
ENET1_TD3: U13.55(TXD[3]) ; port ENET1_TD3
ENET1_TX_CTL: U13.56(TX_CTRL) ; port ENET1_TX_CTL
ENET1_TXC: U13.53(TX_CLK) ; port ENET1_TXC
ETH1_TXRXA_N: J26.3(TRD1-) U13.27(MDIN[0])
ETH1_TXRXA_P: J26.2(TRD1+) U13.28(MDIP[0])
ETH1_TXRXB_N: J26.5(TRD2-) U13.23(MDIN[1])
ETH1_TXRXB_P: J26.4(TRD2+) U13.24(MDIP[1])
ETH1_TXRXC_N: J26.7(TRD3-) U13.21(MDIN[2])
ETH1_TXRXC_P: J26.6(TRD3+) U13.22(MDIP[2])
ETH1_TXRXD_N: J26.9(TRD4-) U13.17(MDIN[3])
ETH1_TXRXD_P: J26.8(TRD4+) U13.18(MDIP[3])
LED_1_1000_1V8: U13.12(LED[2]/INT) U36.4(A2)
LED_1_1000_3V3: J26.D4 U36.1(B2)
LED_1_ACT_1V8: U13.14(LED[0]) U36.5(A1)
LED_1_ACT_3V3: J26.D2 U36.8(B1)
NetC58_2: C58.2 C59.2 L2.1 U13.36(REG_IN)
NetC60_2: C60.2 C61.2 C62.2 L3.1 U13.20(AVDD33) U13.25(AVDD33)
NetC63_2: C63.2 C64.2 C65.2 C66.2 L4.1 U13.10(VDDO_SEL) U13.11(VDDO) U13.49(VDDO) U13.52(VDDO)
NetC67_1: C67.1 R103.1 U13.16(RESET)
NetC68_2: C68.2 U13.34(XTAL_IN) X1.1
NetC69_2: C69.2 C70.2 L5.1 U13.35(AVDDC18)
NetC71_2: C71.2 U13.33(XTAL_OUT) X1.3
NetC72_2: C72.2 C73.2 C74.2 C75.2 C76.2 L6.1 U13.3(AVDD18) U13.19(AVDD18) U13.26(AVDD18) U13.38(AVDD18)
NetC80_1: C80.1 U13.37(REGCAP1)
NetC80_2: C80.2 U13.41(REGCAP2)
NetJ26_D1: J26.D1 R98.2
NetJ26_D3: J26.D3 R97.2
NetR101_2: R101.2 R102.2 U13.15(CONFIG)
NetR106_2: R106.2 U13.30(RSET)
NetR238_2: R238.2 U36.6(OE)
NetTP7_1: TP7.1 U13.9(CLK125)

Not connected (* = marked no-connect by the designer): U13 1(S_INP)* 2(S_INN)* 4(S_OUTP)* 5(S_OUTN)* 13(LED[1])* 29(TSTPT)* 31(HSDACN)* 32(HSDACP)*

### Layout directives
differential pair; differential pair class DIFF100: ETH1_TXRXA_N, ETH1_TXRXA_P, ETH1_TXRXC_N, ETH1_TXRXC_P, ETH1_TXRXD_N, ETH1_TXRXD_P
differential pair; net class DIFF100; differential pair class DIFF100: ETH1_TXRXB_N, ETH1_TXRXB_P

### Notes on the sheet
- CONFIG -> '0'
  PHYADD[0] = 0
  CONFIG -> '1'
  PHYADD[0] = 1

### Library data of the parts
C54 C56 C57 = 1000006: as C30 on sheet 07 - Console, CAN, RS485, RTC
C55 C58 C65 C72 C75 C77 C208 C209 = 1000006: as C27 on sheet 07 - Console, CAN, RS485, RTC
C59 C66 C70 C76 C79 = 1000111: as C26 on sheet 07 - Console, CAN, RS485, RTC
C60 C61 C63 C64 C69 C73 C74 C78 = 1000006: as C29 on sheet 07 - Console, CAN, RS485, RTC
C62 = 1000111: as C50 on sheet 08 - JTAG, SWD, uSD, Mini PCIe, uSIM
C67 = 1001167: CAP CER 1UF 10V 10% X5R 0402
C68 C71 = 1002646: CAP CER 33PF 50V C0G/NP0 0402; Part_Type: Capacitor; Manufacturer: Murata; Manufacturer_Part_Number: GCM1555C1H330JA16D; Digi_PN: 14050400; Component_Life_Cycle_State: Reviewed; Area: 2,12; Voltage: 50; Tolerance: 5%
C80 = 1001883: CAP CER 0.22UF 6.3V X7R 0402; Part_Type: Capacitor; Manufacturer: Taiyo Yuden; Manufacturer_Part_Number: JMK105B7224KV-F; Digi_PN: 14000067; Component_Life_Cycle_State: Reviewed; Area: 2.2; Project: Powerley Energy Bridge; Tolerance: 10%
J26 = 1002612: CONN MAGJACK 1PORT 1000 BASE-T IND; Part_Type: Connector; Manufacturer: XMultiple; Manufacturer_Part_Number: XMG-J1B2211NPA-1-DIG; Digi_PN: 18000772; Component_Life_Cycle_State: Created; Area: 339.5; Project: DIGI CC8X SOM
L2-L6 = 1001175: FERRITE BEAD 120 OHM .35A 0402; Part_Type: Filter; Manufacturer: Wurth Electronics Inc; Manufacturer_Part_Number: 7427927112; Digi_PN: 21000128; Component_Life_Cycle_State: Reviewed; Area: 1,12
R97 R98 = 1001158: as R66 on sheet 07 - Console, CAN, RS485, RTC
R99 R106 = 1000474: RES 4.99K OHM 1/10W 1% 0402 SMD; Part_Type: Resistor; Manufacturer: Panasonic - ECG; Manufacturer_Part_Number: ERJ-2RKF4991X; Digi_PN: 13050860; Component_Life_Cycle_State: CAD Reviewed; Area: 0,95; Power_WV_SRF: 100
R100 = 1000229: RES 0.0 OHM 1/2W 1210 SMD; Part_Type: Resistor; Manufacturer: Vishay Dale; Manufacturer_Part_Number: CRCW12100000Z0EA; Digi_PN: 13050962; Component_Life_Cycle_State: Proven; Area: 11,07
R101 R102 R105 = 1000208: as R73 on sheet 07 - Console, CAN, RS485, RTC
R103 = 1000537: RES 10.0K OHM 1/10W 1% 0402 SMD
R238 = 1000537: as R224 on sheet 07 - Console, CAN, RS485, RTC
TP7-TP9 = CAD0011: TEST POINT 30MIL PAD SMT; Component_Life_Cycle_State: Reviewed; Area: 0,58; Project: CLC
U13 = 1002866: SMIC,Gb Eth phy 0/70°C QFN-56 8x8mm; Part_Type: IC; Manufacturer: Marvell; Digi_PN: ACC-240174; Component_Life_Cycle_State: Created; Area: 64
U36 = 1002597: IC TRANSLATING TXRX 8XSON; Manufacturer: NXP Semiconductors; Manufacturer_Part_Number: NTS0102GT,115; Digi_PN: 16000138; Component_Life_Cycle_State: Reviewed; Area: 3,9
X1 = 1001497: SMCRY,25MHZ 50PPM 20PF RH100 EXT; Part_Type: Crystals-Oscillators; Manufacturer: Raltron; Digi_PN: 20000285; Component_Life_Cycle_State: Reviewed; Area: 3,2

## Sheet 10 - Gigabit Ethernet 2.SchDoc: Gigabit Ethernet 2
size A3; PageSetup: Record=PageOptions¦CenterHorizontal=True¦CenterVertical=True¦PrintScale=0.70¦XCorrection=1.00¦YCorrection=1.00¦PrintKind=0¦BorderSize=5000000¦LeftOffset=0¦BottomOffset=0¦Orientation=2¦PaperLength=4200¦PaperWidth=2970¦Scale=100¦PaperSource=7¦PrintQuality=600¦MediaType=1¦DitherType=10¦PaperKind=A4¦PrintScaleMode=1; Author: Juan Anzola; SheetNumber: 10; SheetTotal: 20
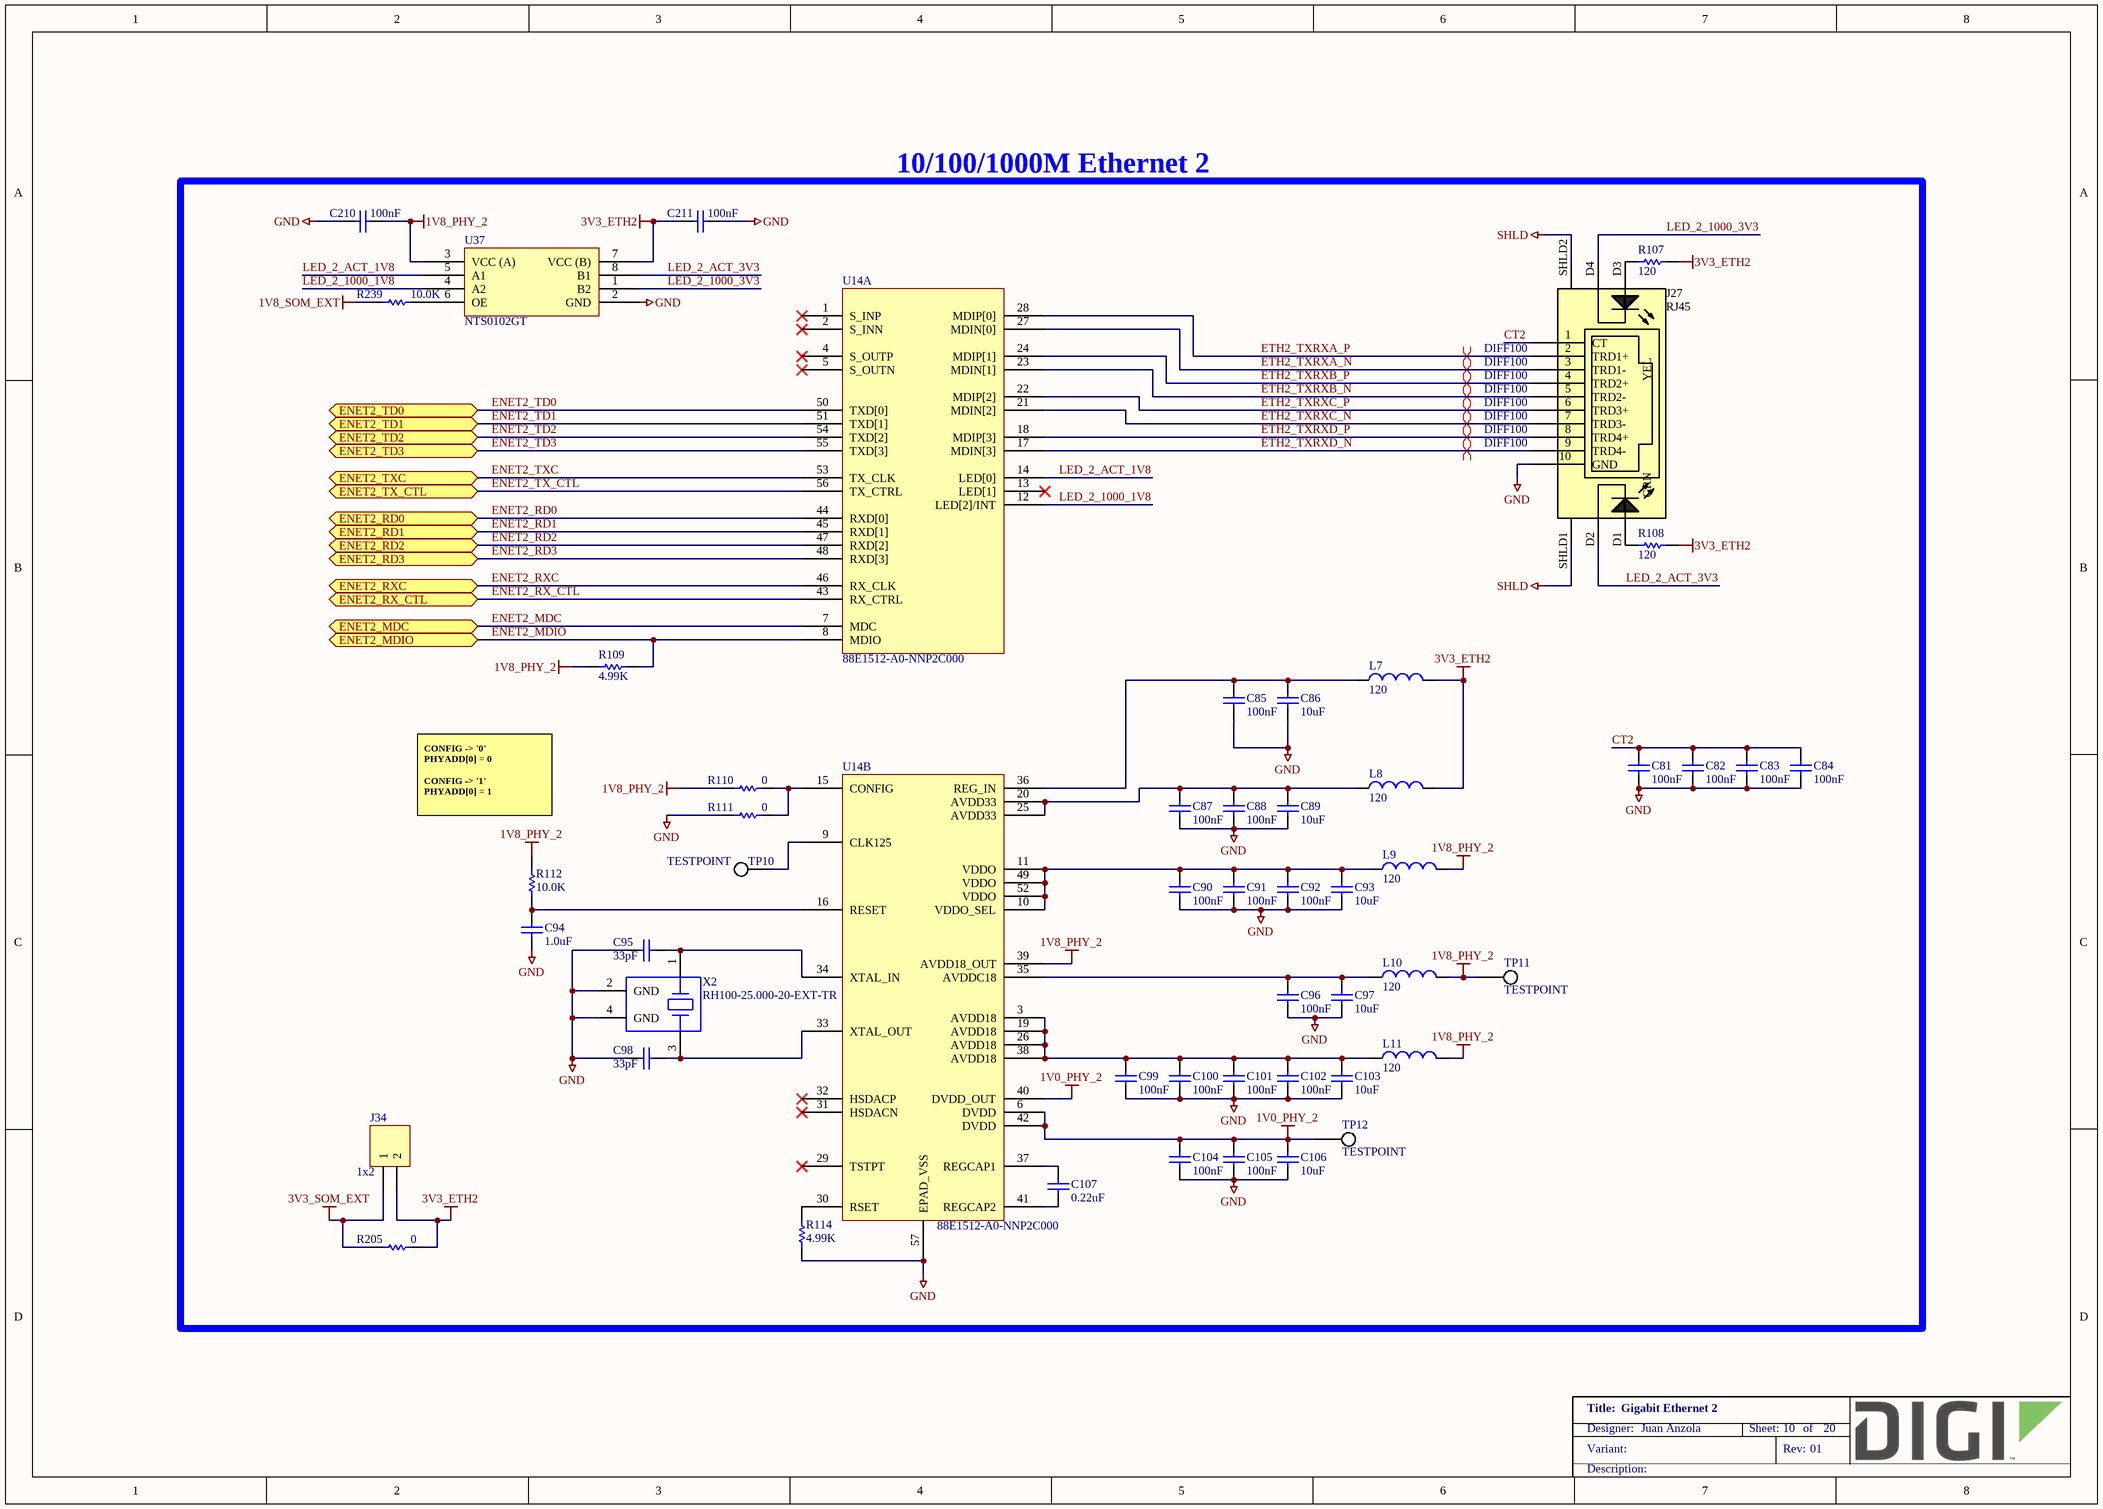
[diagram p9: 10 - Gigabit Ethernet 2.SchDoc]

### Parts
C81  100nF  [CAPC1005X55N]
C82  100nF  [CAPC1005X55N]
C83  100nF  [CAPC1005X55N]
C84  100nF  [CAPC1005X55N]
C85  100nF  [CAPC1005X55N]
C86  10uF  [CAPC2013X135N]
C87  100nF  [CAPC1005X55N]
C88  100nF  [CAPC1005X55N]
C89  10uF  [CAPC2013X135N]
C90  100nF  [CAPC1005X55N]
C91  100nF  [CAPC1005X55N]
C92  100nF  [CAPC1005X55N]
C93  10uF  [CAPC2013X135N]
C94  1.0uF  [CAPC1005X55N]
C95  33pF  [CAPC1005X55N]
C96  100nF  [CAPC1005X55N]
C97  10uF  [CAPC2013X135N]
C98  33pF  [CAPC1005X55N]
C99  100nF  [CAPC1005X55N]
C100  100nF  [CAPC1005X55N]
C101  100nF  [CAPC1005X55N]
C102  100nF  [CAPC1005X55N]
C103  10uF  [CAPC2013X135N]
C104  100nF  [CAPC1005X55N]
C105  100nF  [CAPC1005X55N]
C106  10uF  [CAPC2013X135N]
C107  0.22uF  [CAPC1005X55N]
C210  100nF  [CAPC1005X55N]
C211  100nF  [CAPC1005X55N]
J27  RJ45  [XMULTIPLE_XMG-J1B211]
J34  1x2  [FCI_68002-102HLF]
L7  120  [INDC1005X60N]
L8  120  [INDC1005X60N]
L9  120  [INDC1005X60N]
L10  120  [INDC1005X60N]
L11  120  [INDC1005X60N]
R107  120  [RESC1005X40N]
R108  120  [RESC1005X40N]
R109  4.99K  [RESC1005X40N]
R110  0  [RESC1609X55N]
R111  0  [RESC1609X55N]
R112  10.0K  [RESC1005X40N]
R114  4.99K  [RESC1005X40N]
R205  0  [RESC1609X55N]
R239  10.0K  [RESC1005X40N]
TP10  TESTPOINT  [TP0762]  (no BOM)
TP11  TESTPOINT  [TP0762]  (no BOM)
TP12  TESTPOINT  [TP0762]  (no BOM)
U14  88E1512-A0-NNP2C000  [QFN56P8mmx8mm-4.50mmPAD]  (parts A,B of 2)
U37  NTS0102GT  [PSON50P195X100X50-8N]
X2  RH100-25.000-20-EXT-TR  [OSC210P320X250X90-4N]

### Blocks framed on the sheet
10/100/1000M Ethernet 2: C81-C107 C210 C211 J27 J34 L7-L11 R107-R112 R114 R205 R239 TP10-TP12 U14 U37 X2

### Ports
ENET2_MDC (bidir), ENET2_MDIO (bidir), ENET2_RD0 (bidir), ENET2_RD1 (bidir), ENET2_RD2 (bidir), ENET2_RD3 (bidir), ENET2_RX_CTL (bidir), ENET2_RXC (bidir), ENET2_TD0 (bidir), ENET2_TD1 (bidir), ENET2_TD2 (bidir), ENET2_TD3 (bidir), ENET2_TX_CTL (bidir), ENET2_TXC (bidir)

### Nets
1V0_PHY_2: C104.2 C105.2 C106.2 TP12.1 U14.6(DVDD) U14.40(DVDD_OUT) U14.42(DVDD)
1V8_PHY_2: C210.2 L9.2 L10.2 L11.2 R109.1 R110.1 R112.2 TP11.1 U14.39(AVDD18_OUT) U37.3(VCC_(A))
1V8_SOM_EXT: R239.1
3V3_ETH2: C211.1 J34.2 L7.2 L8.2 R107.1 R108.1 R205.2 U37.7(VCC_(B))
3V3_SOM_EXT: J34.1 R205.1
GND: C81.1 C82.1 C83.1 C84.1 C85.1 C86.1 C87.1 C88.1 C89.1 C90.1 C91.1 C92.1 C93.1 C94.2 C95.1 C96.1 C97.1 C98.1 C99.1 C100.1 C101.1 C102.1 C103.1 C104.1 C105.1 C106.1 C210.1 C211.2 J27.10(GND) R111.1 R114.1 U14.57(EPAD_VSS) U37.2(GND) X2.2(GND) X2.4(GND)
SHLD: J27.SHLD1(SHLD) J27.SHLD2(SHLD)
CT2: C81.2 C82.2 C83.2 C84.2 J27.1(CT)
ENET2_MDC: U14.7(MDC) ; port ENET2_MDC
ENET2_MDIO: R109.2 U14.8(MDIO) ; port ENET2_MDIO
ENET2_RD0: U14.44(RXD[0]) ; port ENET2_RD0
ENET2_RD1: U14.45(RXD[1]) ; port ENET2_RD1
ENET2_RD2: U14.47(RXD[2]) ; port ENET2_RD2
ENET2_RD3: U14.48(RXD[3]) ; port ENET2_RD3
ENET2_RX_CTL: U14.43(RX_CTRL) ; port ENET2_RX_CTL
ENET2_RXC: U14.46(RX_CLK) ; port ENET2_RXC
ENET2_TD0: U14.50(TXD[0]) ; port ENET2_TD0
ENET2_TD1: U14.51(TXD[1]) ; port ENET2_TD1
ENET2_TD2: U14.54(TXD[2]) ; port ENET2_TD2
ENET2_TD3: U14.55(TXD[3]) ; port ENET2_TD3
ENET2_TX_CTL: U14.56(TX_CTRL) ; port ENET2_TX_CTL
ENET2_TXC: U14.53(TX_CLK) ; port ENET2_TXC
ETH2_TXRXA_N: J27.3(TRD1-) U14.27(MDIN[0])
ETH2_TXRXA_P: J27.2(TRD1+) U14.28(MDIP[0])
ETH2_TXRXB_N: J27.5(TRD2-) U14.23(MDIN[1])
ETH2_TXRXB_P: J27.4(TRD2+) U14.24(MDIP[1])
ETH2_TXRXC_N: J27.7(TRD3-) U14.21(MDIN[2])
ETH2_TXRXC_P: J27.6(TRD3+) U14.22(MDIP[2])
ETH2_TXRXD_N: J27.9(TRD4-) U14.17(MDIN[3])
ETH2_TXRXD_P: J27.8(TRD4+) U14.18(MDIP[3])
LED_2_1000_1V8: U14.12(LED[2]/INT) U37.4(A2)
LED_2_1000_3V3: J27.D4 U37.1(B2)
LED_2_ACT_1V8: U14.14(LED[0]) U37.5(A1)
LED_2_ACT_3V3: J27.D2 U37.8(B1)
NetC85_2: C85.2 C86.2 L7.1 U14.36(REG_IN)
NetC87_2: C87.2 C88.2 C89.2 L8.1 U14.20(AVDD33) U14.25(AVDD33)
NetC90_2: C90.2 C91.2 C92.2 C93.2 L9.1 U14.10(VDDO_SEL) U14.11(VDDO) U14.49(VDDO) U14.52(VDDO)
NetC94_1: C94.1 R112.1 U14.16(RESET)
NetC95_2: C95.2 U14.34(XTAL_IN) X2.1
NetC96_2: C96.2 C97.2 L10.1 U14.35(AVDDC18)
NetC98_2: C98.2 U14.33(XTAL_OUT) X2.3
NetC99_2: C99.2 C100.2 C101.2 C102.2 C103.2 L11.1 U14.3(AVDD18) U14.19(AVDD18) U14.26(AVDD18) U14.38(AVDD18)
NetC107_1: C107.1 U14.37(REGCAP1)
NetC107_2: C107.2 U14.41(REGCAP2)
NetJ27_D1: J27.D1 R108.2
NetJ27_D3: J27.D3 R107.2
NetR110_2: R110.2 R111.2 U14.15(CONFIG)
NetR114_2: R114.2 U14.30(RSET)
NetR239_2: R239.2 U37.6(OE)
NetTP10_1: TP10.1 U14.9(CLK125)

Not connected (* = marked no-connect by the designer): U14 1(S_INP)* 2(S_INN)* 4(S_OUTP)* 5(S_OUTN)* 13(LED[1])* 29(TSTPT)* 31(HSDACN)* 32(HSDACP)*

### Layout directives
differential pair; differential pair class DIFF100: ETH2_TXRXA_N, ETH2_TXRXA_P, ETH2_TXRXC_N, ETH2_TXRXC_P, ETH2_TXRXD_N, ETH2_TXRXD_P
differential pair; net class DIFF100; differential pair class DIFF100: ETH2_TXRXB_N, ETH2_TXRXB_P

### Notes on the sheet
- CONFIG -> '0'
  PHYADD[0] = 0
  CONFIG -> '1'
  PHYADD[0] = 1

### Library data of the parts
C81 C84 = 1000006: as C30 on sheet 07 - Console, CAN, RS485, RTC
C82 C83 C85 C102 C105 C210 C211 = 1000006: as C27 on sheet 07 - Console, CAN, RS485, RTC
C86 = 1000111: as C50 on sheet 08 - JTAG, SWD, uSD, Mini PCIe, uSIM
C87 C88 C90-C92 C96 C99-C101 C104 = 1000006: as C29 on sheet 07 - Console, CAN, RS485, RTC
C89 C93 C97 C103 C106 = 1000111: as C26 on sheet 07 - Console, CAN, RS485, RTC
C94 = 1001167: CAP CER 1UF 10V 10% X5R 0402
C95 C98 = 1002646: as C68 on sheet 09 - Gigabit Ethernet 1
C107 = 1001883: as C80 on sheet 09 - Gigabit Ethernet 1
J27 = 1002612: as J26 on sheet 09 - Gigabit Ethernet 1
J34 = 1001128: as J14 on sheet 07 - Console, CAN, RS485, RTC
L7 = 1001175: FERRITE BEAD 120 OHM .35A 0402; Part_Type: Filter; Manufacturer: Wurth Electronics Inc; Manufacturer_Part_Number: 7427927112; Digi_PN: 21000128; Symbol: Inductor; Component_Life_Cycle_State: Reviewed; Area: 1,12; Project: CCWMX6_SBC board
L8-L11 = 1001175: as L2 on sheet 09 - Gigabit Ethernet 1
R107 R108 = 1001158: as R66 on sheet 07 - Console, CAN, RS485, RTC
R109 R114 = 1000474: as R99 on sheet 09 - Gigabit Ethernet 1
R110 R111 R205 = 1000208: as R73 on sheet 07 - Console, CAN, RS485, RTC
R112 = 1000537: RES 10.0K OHM 1/10W 1% 0402 SMD
R239 = 1000537: as R224 on sheet 07 - Console, CAN, RS485, RTC
TP10-TP12 = CAD0011: as TP7-TP9 on sheet 09 - Gigabit Ethernet 1
U14 = 1002866: as U13 on sheet 09 - Gigabit Ethernet 1
U37 = 1002597: as U36 on sheet 09 - Gigabit Ethernet 1
X2 = 1001497: as X1 on sheet 09 - Gigabit Ethernet 1

## Sheet 11 - MIPI switch and display, MIPI camera, LVDS.SchDoc: MIPI switch and display, MIPI camera, LVDS
size A3; PageSetup: Record=PageOptions¦CenterHorizontal=True¦CenterVertical=True¦PrintScale=0.70¦XCorrection=1.00¦YCorrection=1.00¦PrintKind=0¦BorderSize=5000000¦LeftOffset=0¦BottomOffset=0¦Orientation=2¦PaperLength=4200¦PaperWidth=2970¦Scale=100¦PaperSource=7¦PrintQuality=600¦MediaType=1¦DitherType=10¦PaperKind=A4¦PrintScaleMode=1; Author: Juan Anzola; SheetNumber: 11; SheetTotal: 20
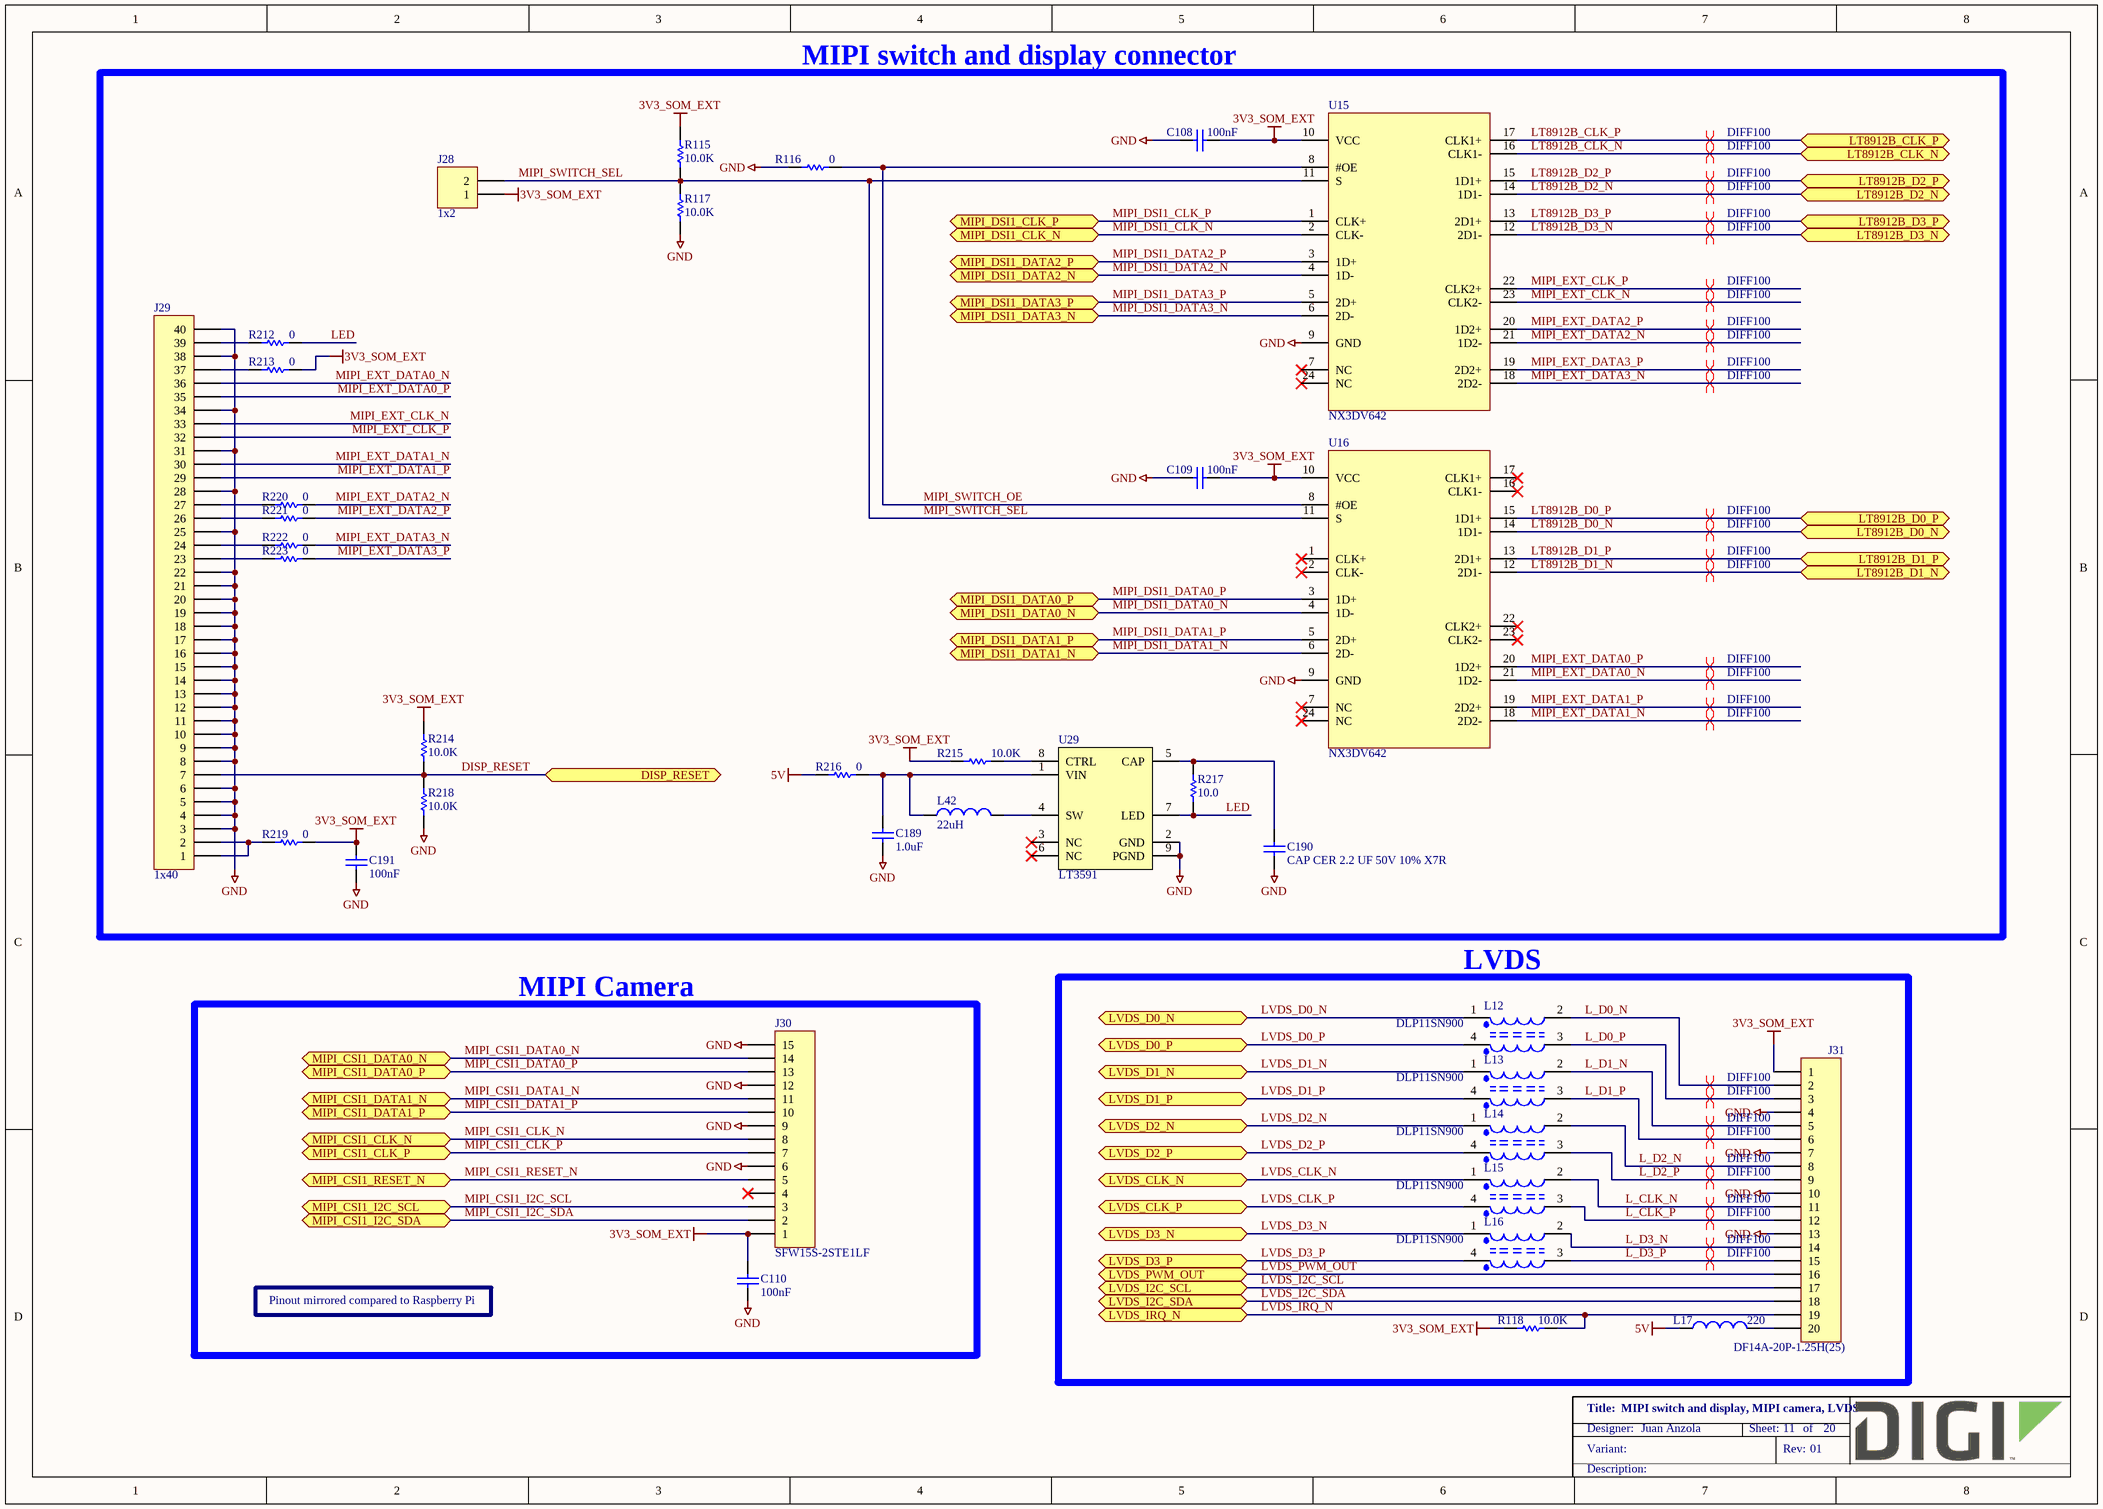
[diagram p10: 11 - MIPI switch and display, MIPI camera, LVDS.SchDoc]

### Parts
C108  100nF  [CAPC1005X55N]
C109  100nF  [CAPC1005X55N]
C110  100nF  [CAPC1005X55N]
C189  1.0uF  [CAPC1005X55N]
C190  CAP CER 2.2 UF 50V 10% X7R  [CAPC3225X250N]
C191  100nF  [CAPC1005X55N]
J28  1x2  [FCI_68002-102HLF]
J29  1x40  [OMRON_XF2M-4015-1A]
J30  SFW15S-2STE1LF  [FCI_SFW15S-2STE1LF]
J31  DF14A-20P-1.25H(25)  [HIROSE_DF14A-20P-1.25H]
L12  DLP11SN900  [FIL_DLP11S]
L13  DLP11SN900  [FIL_DLP11S]
L14  DLP11SN900  [FIL_DLP11S]
L15  DLP11SN900  [FIL_DLP11S]
L16  DLP11SN900  [FIL_DLP11S]
L17  220  [INDC2013X110N]
L42  22uH  [IND_NR4018T220M]
R115  10.0K  [RESC1005X40N]
R116  0  [RESC1609X55N]
R117  10.0K  [RESC1005X40N]
R118  10.0K  [RESC1005X40N]
R212  0  [RESC1005X40N]
R213  0  [RESC1005X40N]
R214  10.0K  [RESC1005X40N]
R215  10.0K  [RESC1005X40N]
R216  0  [RESC1005X40N]
R217  10.0  [RESC1005X40N]
R218  10.0K  [RESC1005X40N]
R219  0  [RESC1005X40N]
R220  0  [RESC1005X40N]
R221  0  [RESC1005X40N]
R222  0  [RESC1005X40N]
R223  0  [RESC1005X40N]
U15  NX3DV642  [QFN40P340X250X50-24N]
U16  NX3DV642  [QFN40P340X250X50-24N]
U29  LT3591  [SON50P300X200X80-9T56X215N]

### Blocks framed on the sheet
MIPI switch and display connector: C108 C109 C189-C191 J28 J29 L42 R115-R117 R212-R223 U15 U16 U29
LVDS: J31 L12-L17 R118
MIPI Camera: C110 J30

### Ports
DISP_RESET (bidir), LT8912B_CLK_N (bidir), LT8912B_CLK_P (bidir), LT8912B_D0_N (bidir), LT8912B_D0_P (bidir), LT8912B_D1_N (bidir), LT8912B_D1_P (bidir), LT8912B_D2_N (bidir), LT8912B_D2_P (bidir), LT8912B_D3_N (bidir), LT8912B_D3_P (bidir), LVDS_CLK_N (bidir), LVDS_CLK_P (bidir), LVDS_D0_N (bidir), LVDS_D0_P (bidir), LVDS_D1_N (bidir), LVDS_D1_P (bidir), LVDS_D2_N (bidir), LVDS_D2_P (bidir), LVDS_D3_N (bidir), LVDS_D3_P (bidir), LVDS_I2C_SCL (bidir), LVDS_I2C_SDA (bidir), LVDS_IRQ_N (bidir), LVDS_PWM_OUT (bidir), MIPI_CSI1_CLK_N (bidir), MIPI_CSI1_CLK_P (bidir), MIPI_CSI1_DATA0_N (bidir), MIPI_CSI1_DATA0_P (bidir), MIPI_CSI1_DATA1_N (bidir), MIPI_CSI1_DATA1_P (bidir), MIPI_CSI1_I2C_SCL (bidir), MIPI_CSI1_I2C_SDA (bidir), MIPI_CSI1_RESET_N (bidir), MIPI_DSI1_CLK_N (bidir), MIPI_DSI1_CLK_P (bidir), MIPI_DSI1_DATA0_N (bidir), MIPI_DSI1_DATA0_P (bidir), MIPI_DSI1_DATA1_N (bidir), MIPI_DSI1_DATA1_P (bidir), MIPI_DSI1_DATA2_N (bidir), MIPI_DSI1_DATA2_P (bidir), MIPI_DSI1_DATA3_N (bidir), MIPI_DSI1_DATA3_P (bidir)

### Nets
3V3_SOM_EXT: C108.1 C109.1 C110.2 C191.2 J28.1 J30.1 J31.1 R115.1 R118.1 R213.2 R214.1 R215.1 R219.2 U15.10(VCC) U16.10(VCC)
5V: L17.1 R216.1
GND: C108.2 C109.2 C110.1 C189.1 C190.1 C191.1 J29.3 J29.4 J29.5 J29.6 J29.8 J29.9 J29.10 J29.11 J29.12 J29.13 J29.14 J29.15 J29.16 J29.17 J29.18 J29.19 J29.20 J29.21 J29.22 J29.25 J29.28 J29.31 J29.34 J29.38 J29.40 J30.6 J30.9 J30.12 J30.15 J31.4 J31.7 J31.10 J31.13 R116.1 R117.2 R218.2 U15.9(GND) U16.9(GND) U29.2(GND) U29.9(PGND)
DISP_RESET: J29.7 R214.2 R218.1 ; port DISP_RESET
L_CLK_N: J31.11 L15.2
L_CLK_P: J31.12 L15.3
L_D0_N: J31.2 L12.2
L_D0_P: J31.3 L12.3
L_D1_N: J31.5 L13.2
L_D1_P: J31.6 L13.3
L_D2_N: J31.8 L14.2
L_D2_P: J31.9 L14.3
L_D3_N: J31.14 L16.2
L_D3_P: J31.15 L16.3
LED: R212.2 R217.1 U29.7(LED)
LT8912B_CLK_N: U15.16(CLK1-) ; port LT8912B_CLK_N
LT8912B_CLK_P: U15.17(CLK1+) ; port LT8912B_CLK_P
LT8912B_D0_N: U16.14(1D1-) ; port LT8912B_D0_N
LT8912B_D0_P: U16.15(1D1+) ; port LT8912B_D0_P
LT8912B_D1_N: U16.12(2D1-) ; port LT8912B_D1_N
LT8912B_D1_P: U16.13(2D1+) ; port LT8912B_D1_P
LT8912B_D2_N: U15.14(1D1-) ; port LT8912B_D2_N
LT8912B_D2_P: U15.15(1D1+) ; port LT8912B_D2_P
LT8912B_D3_N: U15.12(2D1-) ; port LT8912B_D3_N
LT8912B_D3_P: U15.13(2D1+) ; port LT8912B_D3_P
LVDS_CLK_N: L15.1 ; port LVDS_CLK_N
LVDS_CLK_P: L15.4 ; port LVDS_CLK_P
LVDS_D0_N: L12.1 ; port LVDS_D0_N
LVDS_D0_P: L12.4 ; port LVDS_D0_P
LVDS_D1_N: L13.1 ; port LVDS_D1_N
LVDS_D1_P: L13.4 ; port LVDS_D1_P
LVDS_D2_N: L14.1 ; port LVDS_D2_N
LVDS_D2_P: L14.4 ; port LVDS_D2_P
LVDS_D3_N: L16.1 ; port LVDS_D3_N
LVDS_D3_P: L16.4 ; port LVDS_D3_P
LVDS_I2C_SCL: J31.17 ; port LVDS_I2C_SCL
LVDS_I2C_SDA: J31.18 ; port LVDS_I2C_SDA
LVDS_IRQ_N: J31.19 R118.2 ; port LVDS_IRQ_N
LVDS_PWM_OUT: J31.16 ; port LVDS_PWM_OUT
MIPI_CSI1_CLK_N: J30.8 ; port MIPI_CSI1_CLK_N
MIPI_CSI1_CLK_P: J30.7 ; port MIPI_CSI1_CLK_P
MIPI_CSI1_DATA0_N: J30.14 ; port MIPI_CSI1_DATA0_N
MIPI_CSI1_DATA0_P: J30.13 ; port MIPI_CSI1_DATA0_P
MIPI_CSI1_DATA1_N: J30.11 ; port MIPI_CSI1_DATA1_N
MIPI_CSI1_DATA1_P: J30.10 ; port MIPI_CSI1_DATA1_P
MIPI_CSI1_I2C_SCL: J30.3 ; port MIPI_CSI1_I2C_SCL
MIPI_CSI1_I2C_SDA: J30.2 ; port MIPI_CSI1_I2C_SDA
MIPI_CSI1_RESET_N: J30.5 ; port MIPI_CSI1_RESET_N
MIPI_DSI1_CLK_N: U15.2(CLK-) ; port MIPI_DSI1_CLK_N
MIPI_DSI1_CLK_P: U15.1(CLK+) ; port MIPI_DSI1_CLK_P
MIPI_DSI1_DATA0_N: U16.4(1D-) ; port MIPI_DSI1_DATA0_N
MIPI_DSI1_DATA0_P: U16.3(1D+) ; port MIPI_DSI1_DATA0_P
MIPI_DSI1_DATA1_N: U16.6(2D-) ; port MIPI_DSI1_DATA1_N
MIPI_DSI1_DATA1_P: U16.5(2D+) ; port MIPI_DSI1_DATA1_P
MIPI_DSI1_DATA2_N: U15.4(1D-) ; port MIPI_DSI1_DATA2_N
MIPI_DSI1_DATA2_P: U15.3(1D+) ; port MIPI_DSI1_DATA2_P
MIPI_DSI1_DATA3_N: U15.6(2D-) ; port MIPI_DSI1_DATA3_N
MIPI_DSI1_DATA3_P: U15.5(2D+) ; port MIPI_DSI1_DATA3_P
MIPI_EXT_CLK_N: J29.33 U15.23(CLK2-)
MIPI_EXT_CLK_P: J29.32 U15.22(CLK2+)
MIPI_EXT_DATA0_N: J29.36 U16.21(1D2-)
MIPI_EXT_DATA0_P: J29.35 U16.20(1D2+)
MIPI_EXT_DATA1_N: J29.30 U16.18(2D2-)
MIPI_EXT_DATA1_P: J29.29 U16.19(2D2+)
MIPI_EXT_DATA2_N: R220.2 U15.21(1D2-)
MIPI_EXT_DATA2_P: R221.2 U15.20(1D2+)
MIPI_EXT_DATA3_N: R222.2 U15.18(2D2-)
MIPI_EXT_DATA3_P: R223.2 U15.19(2D2+)
MIPI_SWITCH_OE: R116.2 U15.8(#OE) U16.8(#OE)
MIPI_SWITCH_SEL: J28.2 R115.2 R117.1 U15.11(S) U16.11(S)
NetC189_2: C189.2 L42.1 R216.2 U29.1(VIN)
NetC190_2: C190.2 R217.2 U29.5(CAP)
NetJ29_1: J29.1 J29.2 R219.1
NetJ29_23: J29.23 R223.1
NetJ29_24: J29.24 R222.1
NetJ29_26: J29.26 R221.1
NetJ29_27: J29.27 R220.1
NetJ29_37: J29.37 R213.1
NetJ29_39: J29.39 R212.1
NetJ31_20: J31.20 L17.2
NetL42_2: L42.2 U29.4(SW)
NetR215_2: R215.2 U29.8(CTRL)

Not connected (* = marked no-connect by the designer): J30 4*; U15 7(NC)* 24(NC)*; U16 1(CLK+)* 2(CLK-)* 7(NC)* 16(CLK1-)* 17(CLK1+)* 22(CLK2+)* 23(CLK2-)* 24(NC)*; U29 3(NC)* 6(NC)*

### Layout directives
differential pair; net class DIFF100; differential pair class DIFF100: L_CLK_N, L_CLK_P, L_D0_N, L_D0_P, L_D1_N, L_D1_P, L_D2_N, L_D2_P, L_D3_N, L_D3_P, LT8912B_CLK_N, LT8912B_CLK_P, LT8912B_D0_N, LT8912B_D0_P, LT8912B_D1_N, LT8912B_D1_P, LT8912B_D2_N, LT8912B_D2_P, LT8912B_D3_N, LT8912B_D3_P, MIPI_EXT_CLK_N, MIPI_EXT_CLK_P, MIPI_EXT_DATA0_N, MIPI_EXT_DATA0_P, MIPI_EXT_DATA1_N, MIPI_EXT_DATA1_P, MIPI_EXT_DATA2_N, MIPI_EXT_DATA2_P, MIPI_EXT_DATA3_N, MIPI_EXT_DATA3_P

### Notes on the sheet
- Pinout mirrored compared to Raspberry Pi

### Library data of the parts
C108-C110 = 1000006: as C30 on sheet 07 - Console, CAN, RS485, RTC
C189 = 1001167: as C39 on sheet 08 - JTAG, SWD, uSD, Mini PCIe, uSIM
C190 = 1002042: 2.2µF ±10% 50V X7R Ceramic Capacitor -55°C ~ 125°C Surface Mount, MLCC 1210 (3225 Metric) 0.126" L x 0.098" W (3.20mm x 2.50mm); Manufacturer: AVX; Manufacturer_Part_Number: 12105C225KAT2A; Digi_PN: 14050578; Component_Life_Cycle_State: Created; Area: 8
C191 = 1000006: as C27 on sheet 07 - Console, CAN, RS485, RTC
J28 = 1001128: as J14 on sheet 07 - Console, CAN, RS485, RTC
J29 = 1001144: CONN FPC 40POS 0.5MM PITCH SMD; Part_Type: Connector; Manufacturer: Omron; Manufacturer_Part_Number: XF2M-4015-1A; Digi_PN: 18000676; Component_Life_Cycle_State: Reviewed; Area: 117,5
J30 = 1001866: CONN FFC FPC VERT 15POS 1MM SMD; Part_Type: Connector; Manufacturer: FCI; Digi_PN: 18000730; Component_Life_Cycle_State: Reviewed; Area: 128,76; Project: CCiMX6 SBC MFG TEST BOARD
J31 = 1001132: CONN HEADER 20POS 1.25MM R/A SMD; Part_Type: Connector; Manufacturer: Hirose; Digi_PN: 18050231; Component_Life_Cycle_State: Reviewed; Area: 206.34; Project: CCWMX6_SBC board
L12-L16 = 1001014: CHOKE COIL COMMON MODE 150MA SMD; Part_Type: Inductor; Manufacturer: Murata; Manufacturer_Part_Number: DLP11SN900HL2L; Component_Life_Cycle_State: Reviewed; Area: 3.94; Project: ResMed RF Test Interface Board; Digi_PN: 21000531
L17 = 1001174: FERRITE BEAD 220 OHM 2.0A 0805; Manufacturer: Wurth Electronics Inc; Manufacturer_Part_Number: 742792022; Digi_PN: 21000146; Component_Life_Cycle_State: Reviewed; Area: 4.24; Project: CCWMX6_SBC board
L42 = 1002050: FIXED IND 22UH 590MA 432 MOHM; Manufacturer: Taiyo Yuden; Manufacturer_Part_Number: NR4018T220M; Digi_PN: 21000545; Component_Life_Cycle_State: Created; Area: 16
R115 R117 R215 = 1000537: as R224 on sheet 07 - Console, CAN, RS485, RTC
R116 = 1000208: as R73 on sheet 07 - Console, CAN, RS485, RTC
R118 R214 R218 = 1000537: as R72 on sheet 07 - Console, CAN, RS485, RTC
R212 R213 R219 = 1000076: as R65 on sheet 07 - Console, CAN, RS485, RTC
R216 = 1000076: RES 0.0 OHM 1/10W 0402 SMD; Part_Type: Resistor; Manufacturer: Panasonic - ECG; Manufacturer_Part_Number: ERJ-2GE0R00X; Digi_PN: 13050387; Component_Life_Cycle_State: Proven; Area: 0,95; Project: Adjustable Foundation; Power_WV_SRF: 10
R217 = 1000711: RES 10.0 OHM 1/10W 1% 0402 SMD; Part_Type: Resistor; Manufacturer: Panasonic - ECG; Manufacturer_Part_Number: ERJ-2RKF10R0X; Digi_PN: 13051067; Component_Life_Cycle_State: Reviewed; Area: 0,95; Power_WV_SRF: 100
R220-R223 = 1000076: as R68 on sheet 07 - Console, CAN, RS485, RTC
U15 U16 = 1002697: IC SWITCH TPDT DIFF XQFN24; Manufacturer: NXP Semiconductors; Digi_PN: 16000171; Component_Life_Cycle_State: Reviewed; Area: 17,35
U29 = 1002036: LED Driver IC 1 Output DC DC Regulator Step-Up (Boost) PWM Dimming 500mA (Switch) 8-DFN (3x2); Manufacturer: Linear Technology; Manufacturer_Part_Number: LT3591EDDB#TRMPBF; Digi_PN: 17050521; Component_Life_Cycle_State: Created; Area: 6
